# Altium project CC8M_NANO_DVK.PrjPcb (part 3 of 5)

## Sheet 12 - MIPI display and switch, MIPI camera.SchDoc: MIPI display and switch, MIPI camera
size A3; PageSetup: Record=PageOptions¦CenterHorizontal=True¦CenterVertical=True¦PrintScale=0.70¦XCorrection=1.00¦YCorrection=1.00¦PrintKind=0¦BorderSize=5000000¦LeftOffset=0¦BottomOffset=0¦Orientation=2¦PaperLength=4200¦PaperWidth=2970¦Scale=100¦PaperSource=7¦PrintQuality=600¦MediaType=1¦DitherType=10¦PaperKind=A4¦PrintScaleMode=1; Author: Juan Anzola; SheetNumber: 12; SheetTotal: 21
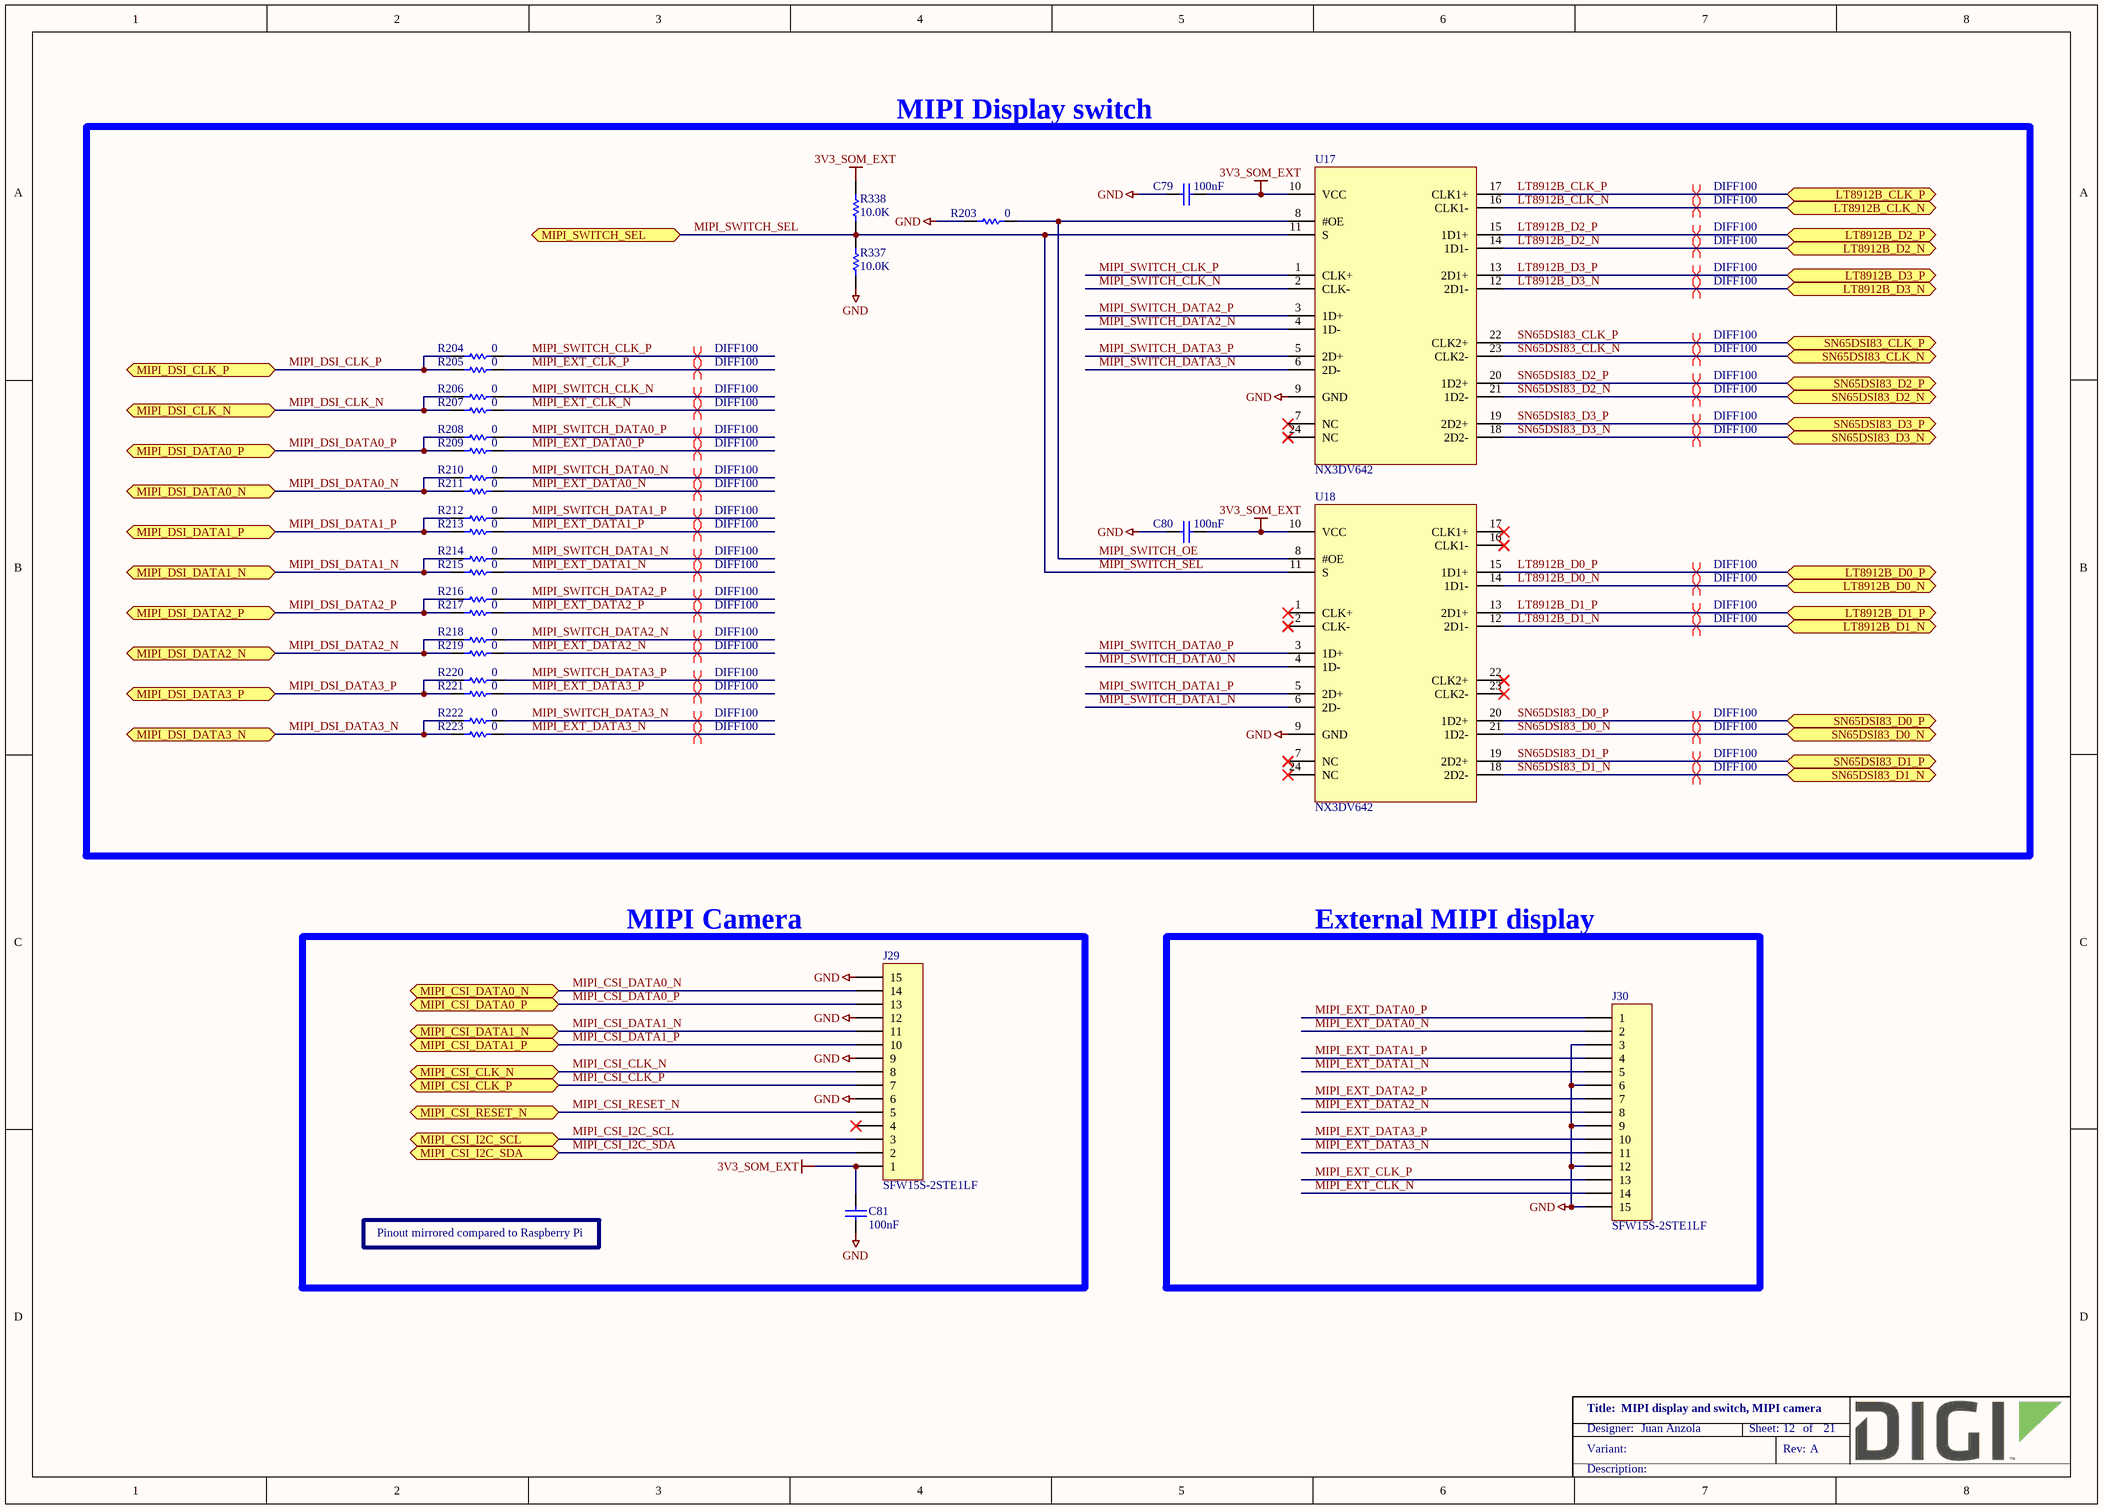
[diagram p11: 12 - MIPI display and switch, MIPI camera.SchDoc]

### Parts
C79  100nF  [CAPC1005X55N]
C80  100nF  [CAPC1005X55N]
C81  100nF  [CAPC1005X55N]
J29  SFW15S-2STE1LF  [FCI_SFW15S-2STE1LF]
J30  SFW15S-2STE1LF  [FCI_SFW15S-2STE1LF]
R203  0  [RESC1609X55N]
R204  0  [RESC1609X55N]
R205  0  [RESC1609X55N]
R206  0  [RESC1609X55N]
R207  0  [RESC1609X55N]
R208  0  [RESC1609X55N]
R209  0  [RESC1609X55N]
R210  0  [RESC1609X55N]
R211  0  [RESC1609X55N]
R212  0  [RESC1609X55N]
R213  0  [RESC1609X55N]
R214  0  [RESC1609X55N]
R215  0  [RESC1609X55N]
R216  0  [RESC1609X55N]
R217  0  [RESC1609X55N]
R218  0  [RESC1609X55N]
R219  0  [RESC1609X55N]
R220  0  [RESC1609X55N]
R221  0  [RESC1609X55N]
R222  0  [RESC1609X55N]
R223  0  [RESC1609X55N]
R337  10.0K  [RESC1005X40N]
R338  10.0K  [RESC1005X40N]
U17  NX3DV642  [QFN40P340X250X50-24N]
U18  NX3DV642  [QFN40P340X250X50-24N]

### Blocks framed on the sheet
MIPI Display switch: C79 C80 R203-R223 R337 R338 U17 U18
MIPI Camera: C81 J29
External MIPI display: J30

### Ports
LT8912B_CLK_N (bidir), LT8912B_CLK_P (bidir), LT8912B_D0_N (bidir), LT8912B_D0_P (bidir), LT8912B_D1_N (bidir), LT8912B_D1_P (bidir), LT8912B_D2_N (bidir), LT8912B_D2_P (bidir), LT8912B_D3_N (bidir), LT8912B_D3_P (bidir), MIPI_CSI_CLK_N (bidir), MIPI_CSI_CLK_P (bidir), MIPI_CSI_DATA0_N (bidir), MIPI_CSI_DATA0_P (bidir), MIPI_CSI_DATA1_N (bidir), MIPI_CSI_DATA1_P (bidir), MIPI_CSI_I2C_SCL (bidir), MIPI_CSI_I2C_SDA (bidir), MIPI_CSI_RESET_N (bidir), MIPI_DSI_CLK_N (bidir), MIPI_DSI_CLK_P (bidir), MIPI_DSI_DATA0_N (bidir), MIPI_DSI_DATA0_P (bidir), MIPI_DSI_DATA1_N (bidir), MIPI_DSI_DATA1_P (bidir), MIPI_DSI_DATA2_N (bidir), MIPI_DSI_DATA2_P (bidir), MIPI_DSI_DATA3_N (bidir), MIPI_DSI_DATA3_P (bidir), MIPI_SWITCH_SEL (bidir), SN65DSI83_CLK_N (bidir), SN65DSI83_CLK_P (bidir), SN65DSI83_D0_N (bidir), SN65DSI83_D0_P (bidir), SN65DSI83_D1_N (bidir), SN65DSI83_D1_P (bidir), SN65DSI83_D2_N (bidir), SN65DSI83_D2_P (bidir), SN65DSI83_D3_N (bidir), SN65DSI83_D3_P (bidir)

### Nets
3V3_SOM_EXT: C79.1 C80.1 C81.2 J29.1 R338.1 U17.10(VCC) U18.10(VCC)
GND: C79.2 C80.2 C81.1 J29.6 J29.9 J29.12 J29.15 J30.3 J30.6 J30.9 J30.12 J30.15 R203.1 R337.2 U17.9(GND) U18.9(GND)
LT8912B_CLK_N: U17.16(CLK1-) ; port LT8912B_CLK_N
LT8912B_CLK_P: U17.17(CLK1+) ; port LT8912B_CLK_P
LT8912B_D0_N: U18.14(1D1-) ; port LT8912B_D0_N
LT8912B_D0_P: U18.15(1D1+) ; port LT8912B_D0_P
LT8912B_D1_N: U18.12(2D1-) ; port LT8912B_D1_N
LT8912B_D1_P: U18.13(2D1+) ; port LT8912B_D1_P
LT8912B_D2_N: U17.14(1D1-) ; port LT8912B_D2_N
LT8912B_D2_P: U17.15(1D1+) ; port LT8912B_D2_P
LT8912B_D3_N: U17.12(2D1-) ; port LT8912B_D3_N
LT8912B_D3_P: U17.13(2D1+) ; port LT8912B_D3_P
MIPI_CSI_CLK_N: J29.8 ; port MIPI_CSI_CLK_N
MIPI_CSI_CLK_P: J29.7 ; port MIPI_CSI_CLK_P
MIPI_CSI_DATA0_N: J29.14 ; port MIPI_CSI_DATA0_N
MIPI_CSI_DATA0_P: J29.13 ; port MIPI_CSI_DATA0_P
MIPI_CSI_DATA1_N: J29.11 ; port MIPI_CSI_DATA1_N
MIPI_CSI_DATA1_P: J29.10 ; port MIPI_CSI_DATA1_P
MIPI_CSI_I2C_SCL: J29.3 ; port MIPI_CSI_I2C_SCL
MIPI_CSI_I2C_SDA: J29.2 ; port MIPI_CSI_I2C_SDA
MIPI_CSI_RESET_N: J29.5 ; port MIPI_CSI_RESET_N
MIPI_DSI_CLK_N: R206.1 R207.1 ; port MIPI_DSI_CLK_N
MIPI_DSI_CLK_P: R204.1 R205.1 ; port MIPI_DSI_CLK_P
MIPI_DSI_DATA0_N: R210.1 R211.1 ; port MIPI_DSI_DATA0_N
MIPI_DSI_DATA0_P: R208.1 R209.1 ; port MIPI_DSI_DATA0_P
MIPI_DSI_DATA1_N: R214.1 R215.1 ; port MIPI_DSI_DATA1_N
MIPI_DSI_DATA1_P: R212.1 R213.1 ; port MIPI_DSI_DATA1_P
MIPI_DSI_DATA2_N: R218.1 R219.1 ; port MIPI_DSI_DATA2_N
MIPI_DSI_DATA2_P: R216.1 R217.1 ; port MIPI_DSI_DATA2_P
MIPI_DSI_DATA3_N: R222.1 R223.1 ; port MIPI_DSI_DATA3_N
MIPI_DSI_DATA3_P: R220.1 R221.1 ; port MIPI_DSI_DATA3_P
MIPI_EXT_CLK_N: J30.14 R207.2
MIPI_EXT_CLK_P: J30.13 R205.2
MIPI_EXT_DATA0_N: J30.2 R211.2
MIPI_EXT_DATA0_P: J30.1 R209.2
MIPI_EXT_DATA1_N: J30.5 R215.2
MIPI_EXT_DATA1_P: J30.4 R213.2
MIPI_EXT_DATA2_N: J30.8 R219.2
MIPI_EXT_DATA2_P: J30.7 R217.2
MIPI_EXT_DATA3_N: J30.11 R223.2
MIPI_EXT_DATA3_P: J30.10 R221.2
MIPI_SWITCH_CLK_N: R206.2 U17.2(CLK-)
MIPI_SWITCH_CLK_P: R204.2 U17.1(CLK+)
MIPI_SWITCH_DATA0_N: R210.2 U18.4(1D-)
MIPI_SWITCH_DATA0_P: R208.2 U18.3(1D+)
MIPI_SWITCH_DATA1_N: R214.2 U18.6(2D-)
MIPI_SWITCH_DATA1_P: R212.2 U18.5(2D+)
MIPI_SWITCH_DATA2_N: R218.2 U17.4(1D-)
MIPI_SWITCH_DATA2_P: R216.2 U17.3(1D+)
MIPI_SWITCH_DATA3_N: R222.2 U17.6(2D-)
MIPI_SWITCH_DATA3_P: R220.2 U17.5(2D+)
MIPI_SWITCH_OE: R203.2 U17.8(#OE) U18.8(#OE)
MIPI_SWITCH_SEL: R337.1 R338.2 U17.11(S) U18.11(S) ; port MIPI_SWITCH_SEL
SN65DSI83_CLK_N: U17.23(CLK2-) ; port SN65DSI83_CLK_N
SN65DSI83_CLK_P: U17.22(CLK2+) ; port SN65DSI83_CLK_P
SN65DSI83_D0_N: U18.21(1D2-) ; port SN65DSI83_D0_N
SN65DSI83_D0_P: U18.20(1D2+) ; port SN65DSI83_D0_P
SN65DSI83_D1_N: U18.18(2D2-) ; port SN65DSI83_D1_N
SN65DSI83_D1_P: U18.19(2D2+) ; port SN65DSI83_D1_P
SN65DSI83_D2_N: U17.21(1D2-) ; port SN65DSI83_D2_N
SN65DSI83_D2_P: U17.20(1D2+) ; port SN65DSI83_D2_P
SN65DSI83_D3_N: U17.18(2D2-) ; port SN65DSI83_D3_N
SN65DSI83_D3_P: U17.19(2D2+) ; port SN65DSI83_D3_P

Not connected (* = marked no-connect by the designer): J29 4*; U17 7(NC)* 24(NC)*; U18 1(CLK+)* 2(CLK-)* 7(NC)* 16(CLK1-)* 17(CLK1+)* 22(CLK2+)* 23(CLK2-)* 24(NC)*

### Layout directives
differential pair; net class DIFF100: LT8912B_CLK_N, LT8912B_CLK_P, LT8912B_D0_N, LT8912B_D0_P, LT8912B_D1_N, LT8912B_D1_P, LT8912B_D2_N, LT8912B_D2_P, LT8912B_D3_N, LT8912B_D3_P, MIPI_EXT_CLK_N, MIPI_EXT_CLK_P, MIPI_EXT_DATA0_N, MIPI_EXT_DATA0_P, MIPI_EXT_DATA1_N, MIPI_EXT_DATA1_P, MIPI_EXT_DATA2_N, MIPI_EXT_DATA2_P, MIPI_EXT_DATA3_N, MIPI_EXT_DATA3_P, MIPI_SWITCH_CLK_N, MIPI_SWITCH_CLK_P, MIPI_SWITCH_DATA0_N, MIPI_SWITCH_DATA0_P, MIPI_SWITCH_DATA1_N, MIPI_SWITCH_DATA1_P, MIPI_SWITCH_DATA2_N, MIPI_SWITCH_DATA2_P, MIPI_SWITCH_DATA3_N, MIPI_SWITCH_DATA3_P, SN65DSI83_CLK_N, SN65DSI83_CLK_P, SN65DSI83_D0_N, SN65DSI83_D0_P, SN65DSI83_D1_N, SN65DSI83_D1_P, SN65DSI83_D2_N, SN65DSI83_D2_P, SN65DSI83_D3_N, SN65DSI83_D3_P

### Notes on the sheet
- Pinout mirrored compared to Raspberry Pi

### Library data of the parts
C79-C81 = 1000006: CAP 100nF 16V 10% X7R 0402; Part_Type: Capacitor; Manufacturer: Murata; Manufacturer_Part_Number: GRM155R71C104KA88D; Digi_PN: 14050552; Component_Life_Cycle_State: CAD Reviewed; Area: 0,95; Project: KITT; Tolerance: 10
J29 J30 = 1001866: CONN FFC FPC VERT 15POS 1MM SMD; Part_Type: Connector; Manufacturer: FCI; Digi_PN: 18000730; Component_Life_Cycle_State: Reviewed; Area: 128,76; Project: CCiMX6 SBC MFG TEST BOARD
R203-R223 = 1000208: RES 0.0 OHM 1/10W 0603; Part_Type: Resistor; Manufacturer: Panasonic - ECG; Manufacturer_Part_Number: ERJ-3GEY0R00V; Note: 13051103 = Digi No. for GE WDNU; Digi_PN: 13050568; Component_Life_Cycle_State: Reviewed; Area: 2,5; Voltage: 75V
R337 R338 = 1000537: RES 10.0K OHM 1/10W 1% 0402 SMD; Part_Type: Resistor; Manufacturer: Panasonic - ECG; Manufacturer_Part_Number: ERJ-2RKF1002X; Digi_PN: 13051084; Component_Life_Cycle_State: CAD Reviewed; Area: 0,95; Power_WV_SRF: 100
U17 U18 = 1002697: IC SWITCH TPDT DIFF XQFN24; Manufacturer: NXP Semiconductors; Digi_PN: 16000171; Component_Life_Cycle_State: Reviewed; Area: 17,35

## Sheet 13 - MIPI to HDMI bridge.SchDoc: MIPI to HDMI bridge
size A3; PageSetup: Record=PageOptions¦CenterHorizontal=True¦CenterVertical=True¦PrintScale=0.70¦XCorrection=1.00¦YCorrection=1.00¦PrintKind=0¦BorderSize=5000000¦LeftOffset=0¦BottomOffset=0¦Orientation=2¦PaperLength=4200¦PaperWidth=2970¦Scale=100¦PaperSource=7¦PrintQuality=600¦MediaType=1¦DitherType=10¦PaperKind=A4¦PrintScaleMode=1; Author: Juan Anzola; SheetNumber: 13; SheetTotal: 21
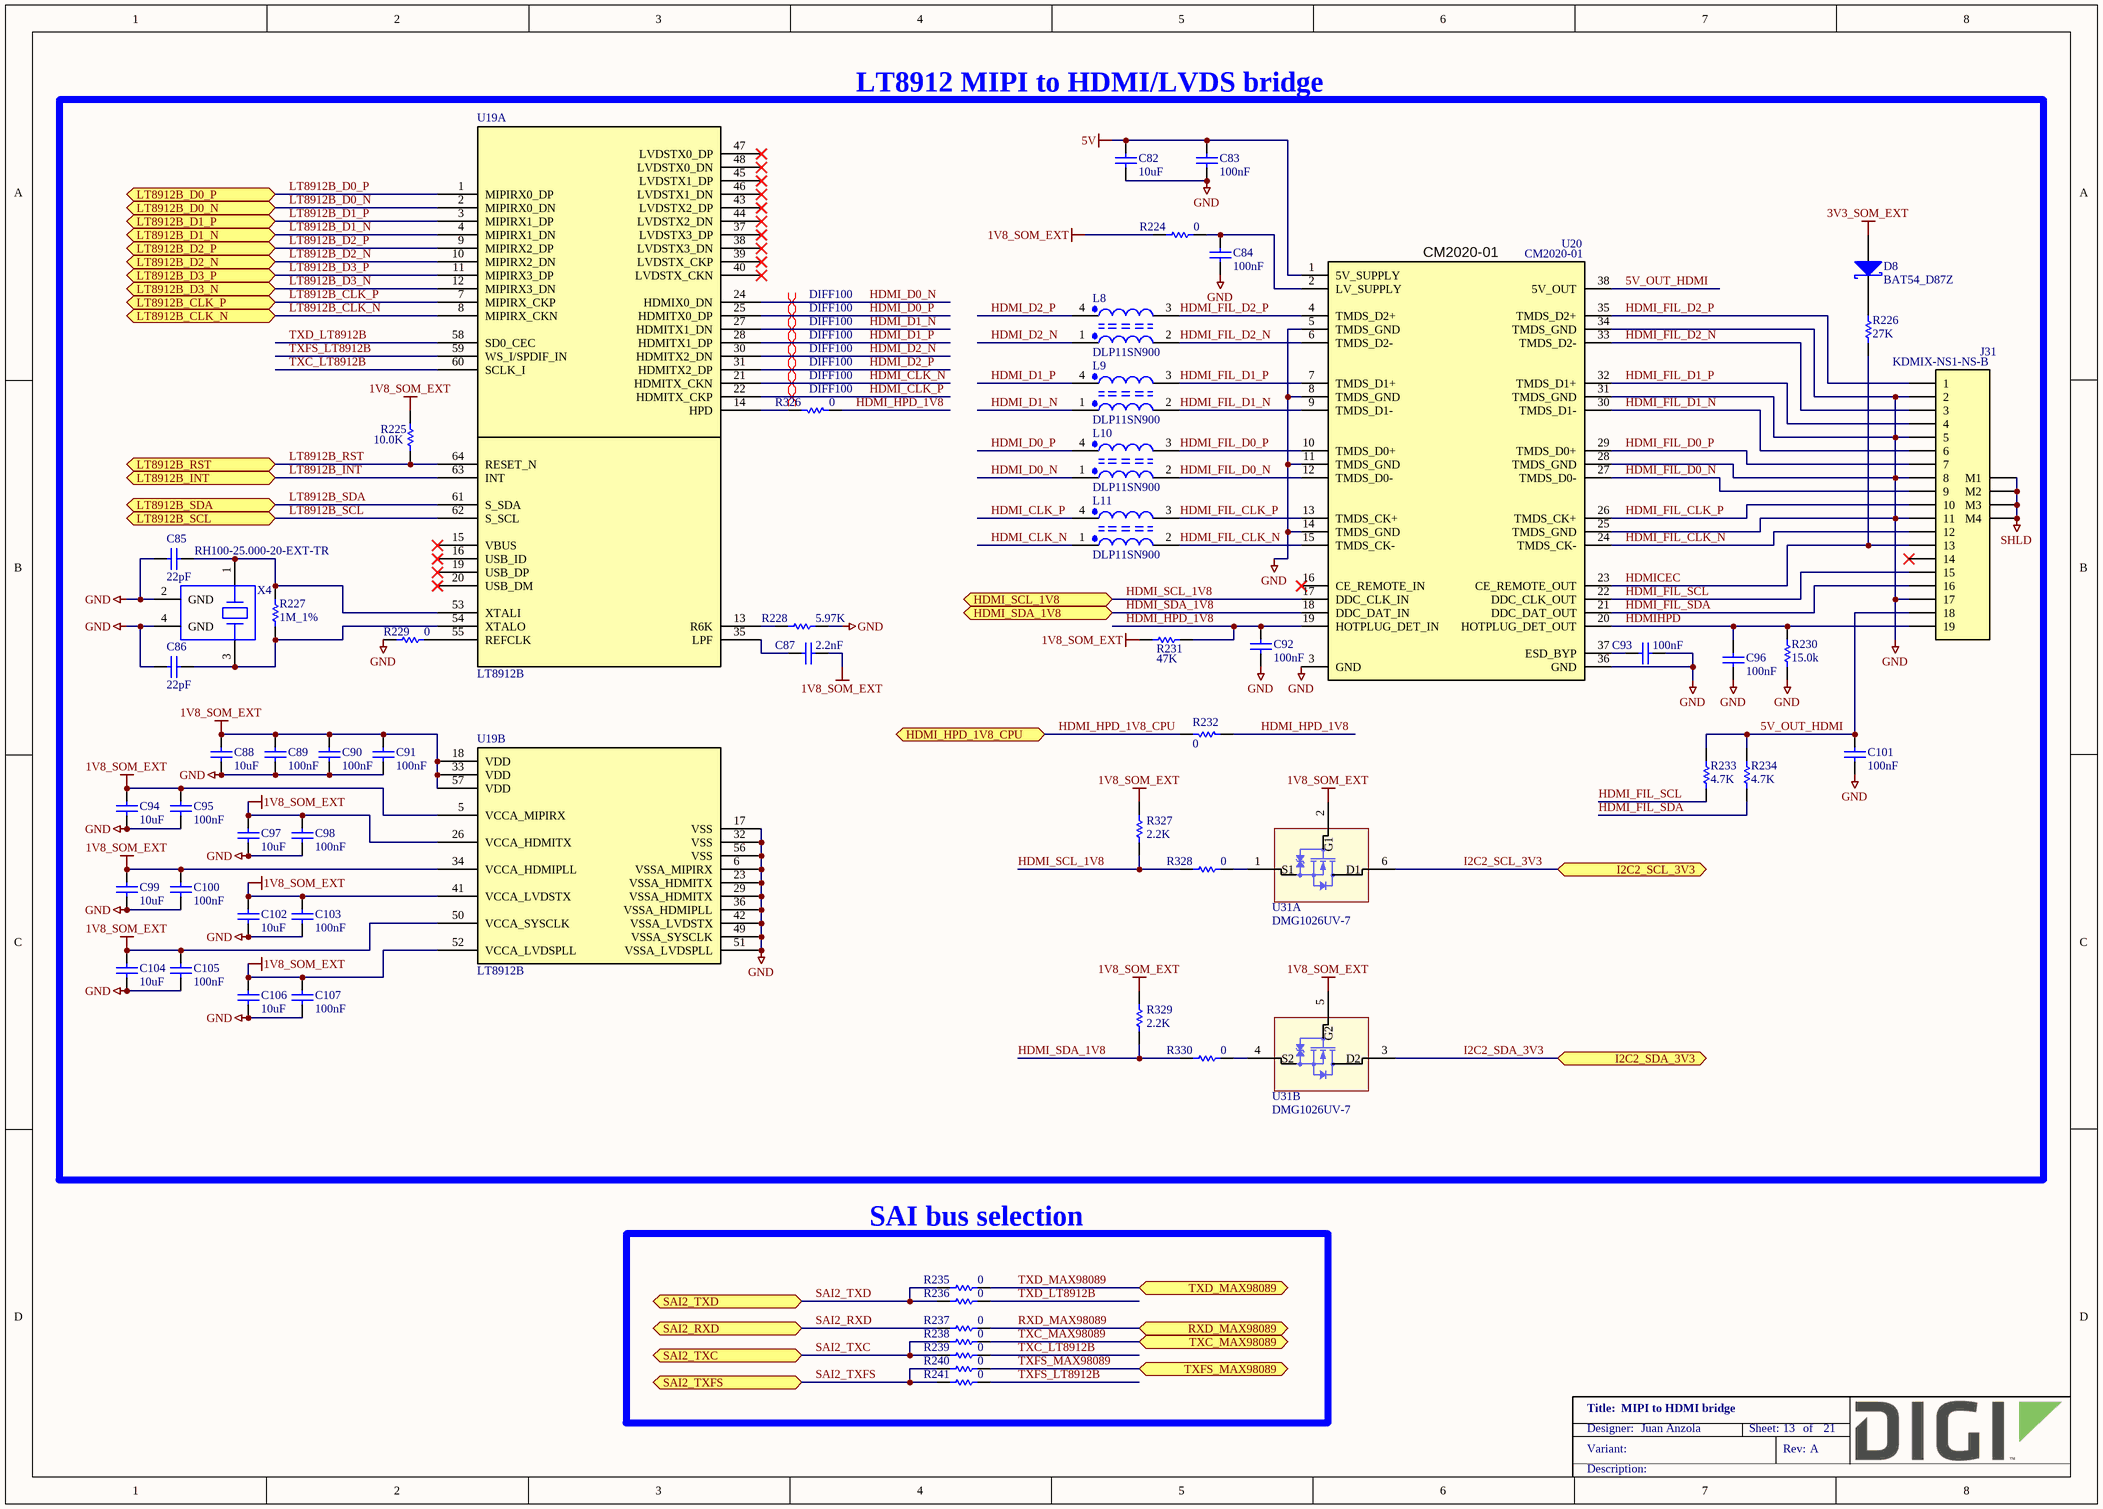
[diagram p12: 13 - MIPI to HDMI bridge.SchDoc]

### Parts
C82  10uF  [CAPC1005X55N]
C83  100nF  [CAPC1005X55N]
C84  100nF  [CAPC1005X55N]
C85  22pF  [CAPC1005X55N]
C86  22pF  [CAPC1005X55N]
C87  2.2nF  [CAPC1608X90N]
C88  10uF  [CAPC1005X55N]
C89  100nF  [CAPC1005X55N]
C90  100nF  [CAPC1005X55N]
C91  100nF  [CAPC1005X55N]
C92  100nF  [CAPC1005X55N]
C93  100nF  [CAPC1005X55N]
C94  10uF  [CAPC1005X55N]
C95  100nF  [CAPC1005X55N]
C96  100nF  [CAPC1005X55N]
C97  10uF  [CAPC1005X55N]
C98  100nF  [CAPC1005X55N]
C99  10uF  [CAPC1005X55N]
C100  100nF  [CAPC1005X55N]
C101  100nF  [CAPC1005X55N]
C102  10uF  [CAPC1005X55N]
C103  100nF  [CAPC1005X55N]
C104  10uF  [CAPC1005X55N]
C105  100nF  [CAPC1005X55N]
C106  10uF  [CAPC1005X55N]
C107  100nF  [CAPC1005X55N]
D8  BAT54_D87Z  [SOT95P240X110_AXK-3N]
J31  KDMIX-NS1-NS-B  [KYCON_KDMIX]
L8  DLP11SN900  [FIL_DLP11S]
L9  DLP11SN900  [FIL_DLP11S]
L10  DLP11SN900  [FIL_DLP11S]
L11  DLP11SN900  [FIL_DLP11S]
R224  0  [RESC1005X40N]
R225  10.0K  [RESC1005X40N]
R226  27K  [RESC1005X40N]
R227  1M_1%  [RESC1005X40N]
R228  5.97K  [RESC1005X40N]
R229  0  [RESC1005X40N]
R230  15.0k  [RESC1005X40N]
R231  47K  [RESC1005X40N]
R232  0  [RESC1005X40N]
R233  4.7K  [RESC1005X40N]
R234  4.7K  [RESC1005X40N]
R235  0  [RESC1609X55N]
R236  0  [RESC1609X55N]
R237  0  [RESC1609X55N]
R238  0  [RESC1609X55N]
R239  0  [RESC1609X55N]
R240  0  [RESC1609X55N]
R241  0  [RESC1609X55N]
R326  0  [RESC1005X40N]
R327  2.2K  [RESC1005X40N]
R328  0  [RESC1005X40N]
R329  2.2K  [RESC1005X40N]
R330  0  [RESC1005X40N]
U19  LT8912B  [QFN40P750X750X80-64N]  (parts A,B of 2)
U20  CM2020-01  [SOP50P640X120-38N]
U31  DMG1026UV-7  [SOTFL50P160X60-6N]  (parts A,B of 2)
X4  RH100-25.000-20-EXT-TR  [OSC210P320X250X90-4N]

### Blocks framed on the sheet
LT8912 MIPI to HDMI/LVDS bridge: C82-C107 D8 J31 L8-L11 R224-R234 R326-R330 U19 U20 U31 X4
SAI bus selection: R235-R241

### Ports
HDMI_HPD_1V8_CPU (bidir), HDMI_SCL_1V8 (bidir), HDMI_SDA_1V8 (bidir), I2C2_SCL_3V3 (bidir), I2C2_SDA_3V3 (bidir), LT8912B_CLK_N (bidir), LT8912B_CLK_P (bidir), LT8912B_D0_N (bidir), LT8912B_D0_P (bidir), LT8912B_D1_N (bidir), LT8912B_D1_P (bidir), LT8912B_D2_N (bidir), LT8912B_D2_P (bidir), LT8912B_D3_N (bidir), LT8912B_D3_P (bidir), LT8912B_INT (bidir), LT8912B_RST (bidir), LT8912B_SCL (bidir), LT8912B_SDA (bidir), RXD_MAX98089 (bidir), SAI2_RXD (bidir), SAI2_TXC (bidir), SAI2_TXD (bidir), SAI2_TXFS (bidir), TXC_MAX98089 (bidir), TXD_MAX98089 (bidir), TXFS_MAX98089 (bidir)

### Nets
1V8_SOM_EXT: C87.2 C88.2 C89.2 C90.2 C91.2 C94.2 C95.2 C97.2 C98.2 C99.2 C100.2 C102.2 C103.2 C104.2 C105.2 C106.2 C107.2 R224.2 R225.1 R231.1 R327.2 R329.2 U19.5(VCCA_MIPIRX) U19.18(VDD) U19.26(VCCA_HDMITX) U19.33(VDD) U19.34(VCCA_HDMIPLL) U19.41(VCCA_LVDSTX) U19.50(VCCA_SYSCLK) U19.52(VCCA_LVDSPLL) U19.57(VDD) U31.2(G1) U31.5(G2)
3V3_SOM_EXT: D8.A
5V: C82.2 C83.2 U20.1(5V_SUPPLY)
GND: C82.1 C83.1 C84.1 C85.1 C86.1 C88.1 C89.1 C90.1 C91.1 C92.1 C93.1 C94.1 C95.1 C96.1 C97.1 C98.1 C99.1 C100.1 C101.1 C102.1 C103.1 C104.1 C105.1 C106.1 C107.1 J31.2 J31.5 J31.8 J31.11 J31.17 R228.2 R229.1 R230.1 U19.6(VSSA_MIPIRX) U19.17(VSS) U19.23(VSSA_HDMITX) U19.29(VSSA_HDMITX) U19.32(VSS) U19.36(VSSA_HDMIPLL) U19.42(VSSA_LVDSTX) U19.49(VSSA_SYSCLK) U19.51(VSSA_LVDSPLL) U19.56(VSS) U20.3(GND) U20.5(TMDS_GND) U20.8(TMDS_GND) U20.11(TMDS_GND) U20.14(TMDS_GND) U20.25(TMDS_GND) U20.28(TMDS_GND) U20.31(TMDS_GND) U20.34(TMDS_GND) U20.36(GND) X4.2(GND) X4.4(GND)
SHLD: J31.M1 J31.M2 J31.M3 J31.M4
5V_OUT_HDMI: C101.2 J31.18 R233.1 R234.1 U20.38(5V_OUT)
HDMI_CLK_N: L11.1 U19.21(HDMITX_CKN)
HDMI_CLK_P: L11.4 U19.22(HDMITX_CKP)
HDMI_D0_N: L10.1 U19.24(HDMIX0_DN)
HDMI_D0_P: L10.4 U19.25(HDMITX0_DP)
HDMI_D1_N: L9.1 U19.27(HDMITX1_DN)
HDMI_D1_P: L9.4 U19.28(HDMITX1_DP)
HDMI_D2_N: L8.1 U19.30(HDMITX2_DN)
HDMI_D2_P: L8.4 U19.31(HDMITX2_DP)
HDMI_FIL_CLK_N: J31.12 L11.2 U20.15(TMDS_CK-) U20.24(TMDS_CK-)
HDMI_FIL_CLK_P: J31.10 L11.3 U20.13(TMDS_CK+) U20.26(TMDS_CK+)
HDMI_FIL_D0_N: J31.9 L10.2 U20.12(TMDS_D0-) U20.27(TMDS_D0-)
HDMI_FIL_D0_P: J31.7 L10.3 U20.10(TMDS_D0+) U20.29(TMDS_D0+)
HDMI_FIL_D1_N: J31.6 L9.2 U20.9(TMDS_D1-) U20.30(TMDS_D1-)
HDMI_FIL_D1_P: J31.4 L9.3 U20.7(TMDS_D1+) U20.32(TMDS_D1+)
HDMI_FIL_D2_N: J31.3 L8.2 U20.6(TMDS_D2-) U20.33(TMDS_D2-)
HDMI_FIL_D2_P: J31.1 L8.3 U20.4(TMDS_D2+) U20.35(TMDS_D2+)
HDMI_FIL_SCL: J31.15 R233.2 U20.22(DDC_CLK_OUT)
HDMI_FIL_SDA: J31.16 R234.2 U20.21(DDC_DAT_OUT)
HDMI_HPD_1V8: C92.2 R231.2 R232.1 R326.1 U20.19(HOTPLUG_DET_IN)
HDMI_HPD_1V8_CPU: R232.2 ; port HDMI_HPD_1V8_CPU
HDMI_SCL_1V8: R327.1 R328.1 U20.17(DDC_CLK_IN) ; port HDMI_SCL_1V8
HDMI_SDA_1V8: R329.1 R330.1 U20.18(DDC_DAT_IN) ; port HDMI_SDA_1V8
HDMICEC: J31.13 R226.2 U20.23(CE_REMOTE_OUT)
HDMIHPD: C96.2 J31.19 R230.2 U20.20(HOTPLUG_DET_OUT)
I2C2_SCL_3V3: U31.6(D1) ; port I2C2_SCL_3V3
I2C2_SDA_3V3: U31.3(D2) ; port I2C2_SDA_3V3
LT8912B_CLK_N: U19.8(MIPIRX_CKN) ; port LT8912B_CLK_N
LT8912B_CLK_P: U19.7(MIPIRX_CKP) ; port LT8912B_CLK_P
LT8912B_D0_N: U19.2(MIPIRX0_DN) ; port LT8912B_D0_N
LT8912B_D0_P: U19.1(MIPIRX0_DP) ; port LT8912B_D0_P
LT8912B_D1_N: U19.4(MIPIRX1_DN) ; port LT8912B_D1_N
LT8912B_D1_P: U19.3(MIPIRX1_DP) ; port LT8912B_D1_P
LT8912B_D2_N: U19.10(MIPIRX2_DN) ; port LT8912B_D2_N
LT8912B_D2_P: U19.9(MIPIRX2_DP) ; port LT8912B_D2_P
LT8912B_D3_N: U19.12(MIPIRX3_DN) ; port LT8912B_D3_N
LT8912B_D3_P: U19.11(MIPIRX3_DP) ; port LT8912B_D3_P
LT8912B_INT: U19.63(INT) ; port LT8912B_INT
LT8912B_RST: R225.2 U19.64(RESET_N) ; port LT8912B_RST
LT8912B_SCL: U19.62(S_SCL) ; port LT8912B_SCL
LT8912B_SDA: U19.61(S_SDA) ; port LT8912B_SDA
RXD_MAX98089: R237.2 ; port RXD_MAX98089
SAI2_RXD: R237.1 ; port SAI2_RXD
SAI2_TXC: R238.1 R239.1 ; port SAI2_TXC
SAI2_TXD: R235.1 R236.1 ; port SAI2_TXD
SAI2_TXFS: R240.1 R241.1 ; port SAI2_TXFS
TXC_LT8912B: R239.2 U19.60(SCLK_I)
TXC_MAX98089: R238.2 ; port TXC_MAX98089
TXD_LT8912B: R236.2 U19.58(SD0_CEC)
TXD_MAX98089: R235.2 ; port TXD_MAX98089
TXFS_LT8912B: R241.2 U19.59(WS_I/SPDIF_IN)
TXFS_MAX98089: R240.2 ; port TXFS_MAX98089
NetC84_2: C84.2 R224.1 U20.2(LV_SUPPLY)
NetC85_2: C85.2 R227.2 U19.53(XTALI) X4.1
NetC86_2: C86.2 R227.1 U19.54(XTALO) X4.3
NetC87_1: C87.1 U19.35(LPF)
NetC93_2: C93.2 U20.37(ESD_BYP)
NetD8_K: D8.K R226.1
NetR228_1: R228.1 U19.13(R6K)
NetR229_2: R229.2 U19.55(REFCLK)
NetR326_2: R326.2 U19.14(HPD)
NetR328_2: R328.2 U31.1(S1)
NetR330_2: R330.2 U31.4(S2)

Not connected (* = marked no-connect by the designer): J31 14*; U19 15(VBUS)* 16(USB_ID)* 19(USB_DP)* 20(USB_DM)* 37(LVDSTX3_DP)* 38(LVDSTX3_DN)* 39(LVDSTX_CKP)* 40(LVDSTX_CKN)* 43(LVDSTX2_DP)* 44(LVDSTX2_DN)* 45(LVDSTX1_DP)* 46(LVDSTX1_DN)* 47(LVDSTX0_DP)* 48(LVDSTX0_DN)*; U20 16(CE_REMOTE_IN)*

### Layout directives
differential pair; net class DIFF100: HDMI_CLK_N, HDMI_CLK_P, HDMI_D0_N, HDMI_D0_P, HDMI_D1_N, HDMI_D1_P, HDMI_D2_N, HDMI_D2_P

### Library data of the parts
C82 C88 C94 C97 C99 C102 C104 C106 = 1001168: CAP CER 10UF 10V 20% X5R 0402; Part_Type: Capacitor; Manufacturer: Samsung; Manufacturer_Part_Number: CL05A106MP5NUNC; Digi_PN: 14050689; Component_Life_Cycle_State: Reviewed; Area: 0.95; Project: CCWMX6_SBC board
C83 C84 C89-C93 C95 C96 C98 C100 C101 C103 C105 C107 = 1000006: CAP 100nF 16V 10% X7R 0402; Part_Type: Capacitor; Manufacturer: Murata; Manufacturer_Part_Number: GRM155R71C104KA88D; Component_Life_Cycle_State: CAD Reviewed; Area: 0.95; Project: KITT; Tolerance: 10; Digi_PN: 14050552
C85 C86 = 1001166: CAP CER 22PF 50V 5% NP0 0402; Part_Type: Capacitor; Manufacturer: Murata; Manufacturer_Part_Number: GRM1555C1H220JA01D; Note: 14050749 = Digi No. for GE WDNU; Digi_PN: 14050367; Component_Life_Cycle_State: Reviewed; Area: 0,95; Project: CCWMX6_SBC board; Temp_Coef: C0G, NP0
C87 = 1002727: CAP CER 2200PF 50V X7R 5% 0603; Part_Type: Capacitor; Manufacturer: Kemet; Manufacturer_Part_Number: C0603C222J5RACTU; Digi_PN: 14050443; Component_Life_Cycle_State: Pending; Area: 2,27
D8 = 1001169: DIODE SCHOTTKY 30V 0.2A SOT23-3; Part_Type: IC; Manufacturer: Fairchild Semiconductor; Digi_PN: 17050507; Component_Life_Cycle_State: Reviewed; Area: 8; Project: CCWMX6_SBC board
J31 = 1001123: HDMI RECEPTACLE, SMT; Part_Type: Connector; Manufacturer: KYCON; Digi_PN: 18000451; Component_Life_Cycle_State: Reviewed; Area: 174; Project: CCWMX6_SBC board
L8-L11 = 1001014: CHOKE COIL COMMON MODE 150MA SMD; Part_Type: Inductor; Manufacturer: Murata; Manufacturer_Part_Number: DLP11SN900HL2L; Component_Life_Cycle_State: Reviewed; Area: 3.94; Project: ResMed RF Test Interface Board; Digi_PN: 21000531
R224 R229 R232 R326 = 1000076: RES 0.0 OHM 1/10W 0402 SMD; Part_Type: Resistor; Manufacturer: Panasonic - ECG; Manufacturer_Part_Number: ERJ-2GE0R00X; Digi_PN: 13050387; Component_Life_Cycle_State: Proven; Area: 0,95; Project: Adjustable Foundation; Power_WV_SRF: 10
R225 = 1000537: RES 10.0K OHM 1/10W 1% 0402 SMD; Part_Type: Resistor; Manufacturer: Panasonic - ECG; Manufacturer_Part_Number: ERJ-2RKF1002X; Component_Life_Cycle_State: CAD Reviewed; Area: 0.95; Project: KITT; Power_WV_SRF: 100; Digi_PN: 13051084
R226 = 1001153: RES 27.0K OHM 1/16W 1% 0402 SMD; Part_Type: Resistor; Manufacturer: Yageo; Manufacturer_Part_Number: RC0402FR-0727KL; Digi_PN: 13050609; Component_Life_Cycle_State: Reviewed; Area: 0.95; Project: CCWMX6_SBC board
R227 = 1000971: RES 1.00M OHM 1/16W 1% 0402 SMD; Part_Type: Resistor; Manufacturer: Yageo; Manufacturer_Part_Number: RC0402FR-071ML; Note: 13051098 = Digi No. for GE WDNU; Digi_PN: 13050561; Component_Life_Cycle_State: Reviewed; Area: 0,95; Power_WV_SRF: 63; Tolerance: 1
R228 = 1002748: RES 5.97K OHM 0.1% 1/10W 0402; Part_Type: Resistor; Manufacturer: Vishay Dale; Manufacturer_Part_Number: TNPW04025K97BEED; Digi_PN: 13000099; Component_Life_Cycle_State: Created; Area: 0,95
R230 = 1000174: RES 15.0K OHM 1/10W 1% 0402 SMD; Part_Type: Resistor; Manufacturer: Panasonic - ECG; Manufacturer_Part_Number: ERJ-2RKF1502X; Component_Life_Cycle_State: CAD Reviewed; Area: 0.95; Project: KITT; Power_WV_SRF: 10; Digi_PN: 13050446
R231 = 1001155: RES 47.0K OHM 1/16W 1% 0402 SMD; Part_Type: Resistor; Manufacturer: Vishay Dale; Manufacturer_Part_Number: CRCW040247K0FKED; Digi_PN: 13050646; Component_Life_Cycle_State: Reviewed; Area: 0.95; Project: CCWMX6_SBC board
R233 R234 = 1000038: RES 4.7K OHM 1/10W 5% 0402 SMD; Part_Type: Resistor; Manufacturer: Panasonic - ECG; Manufacturer_Part_Number: ERJ-2GEJ472X; Component_Life_Cycle_State: Proven; Area: 0.95; Project: Adjustable Foundation; Power_WV_SRF: 100; Tolerance: 5; Digi_PN: 13050549
R235-R241 = 1000208: as R203-R223 on sheet 12 - MIPI display and switch, MIPI camera
R327 R329 = 1001156: RES 2.20K OHM 1/16W 1% 0402 SMD; Part_Type: Resistor; Manufacturer: Yageo; Manufacturer_Part_Number: RC0402FR-072K2L; Digi_PN: 13050699; Component_Life_Cycle_State: Reviewed; Area: 0.95; Project: CCWMX6_SBC board; Note: 13051099 = Digi No. for GE WDNU
R328 R330 = 1000076: RES 0.0 OHM 1/10W 0402 SMD; Part_Type: Resistor; Manufacturer: Panasonic - ECG; Manufacturer_Part_Number: ERJ-2GE0R00X; Component_Life_Cycle_State: Proven; Area: 0.95; Project: Adjustable Foundation; Power_WV_SRF: 10; Digi_PN: 13050387
U19 = 1002722: MIPI DSI BRIDGE TO LVDS/HDMI SINGLE CHANNEL; Part_Type: IC; Manufacturer: Lontium Semiconductor; Digi_PN: 16000199; Component_Life_Cycle_State: Pending; Area: 76,04
U20 = 1001125: IC HDMI XMITTER PORT P/I 38TSSOP; Manufacturer: On Semiconductor; Digi_PN: 16051861; Component_Life_Cycle_State: Reviewed; Area: 43; Project: CCWMX6_SBC board
U31 = 1001009: MOSFET DL N-CH 60V 410MA SOT-563; Part_Type: Transistor; Manufacturer: Diodes, Inc.; Digi_PN: 17050796; Component_Life_Cycle_State: Reviewed; Area: 2,89; Project: ConnectCore i.MX6 module
X4 = 1001497: SMCRY,25MHZ 50PPM 20PF RH100 EXT; Part_Type: Crystals-Oscillators; Manufacturer: Raltron; Digi_PN: 20000285; Component_Life_Cycle_State: Reviewed; Area: 3,2; Project: CCWMX6_SBC board

## Sheet 14 - MIPI to LVDS bridge.SchDoc: MIPI to LVDS bridge
size A3; PageSetup: Record=PageOptions¦CenterHorizontal=True¦CenterVertical=True¦PrintScale=0.70¦XCorrection=1.00¦YCorrection=1.00¦PrintKind=0¦BorderSize=5000000¦LeftOffset=0¦BottomOffset=0¦Orientation=2¦PaperLength=4200¦PaperWidth=2970¦Scale=100¦PaperSource=7¦PrintQuality=600¦MediaType=1¦DitherType=10¦PaperKind=A4¦PrintScaleMode=1; Author: Juan Anzola; SheetNumber: 14; SheetTotal: 21
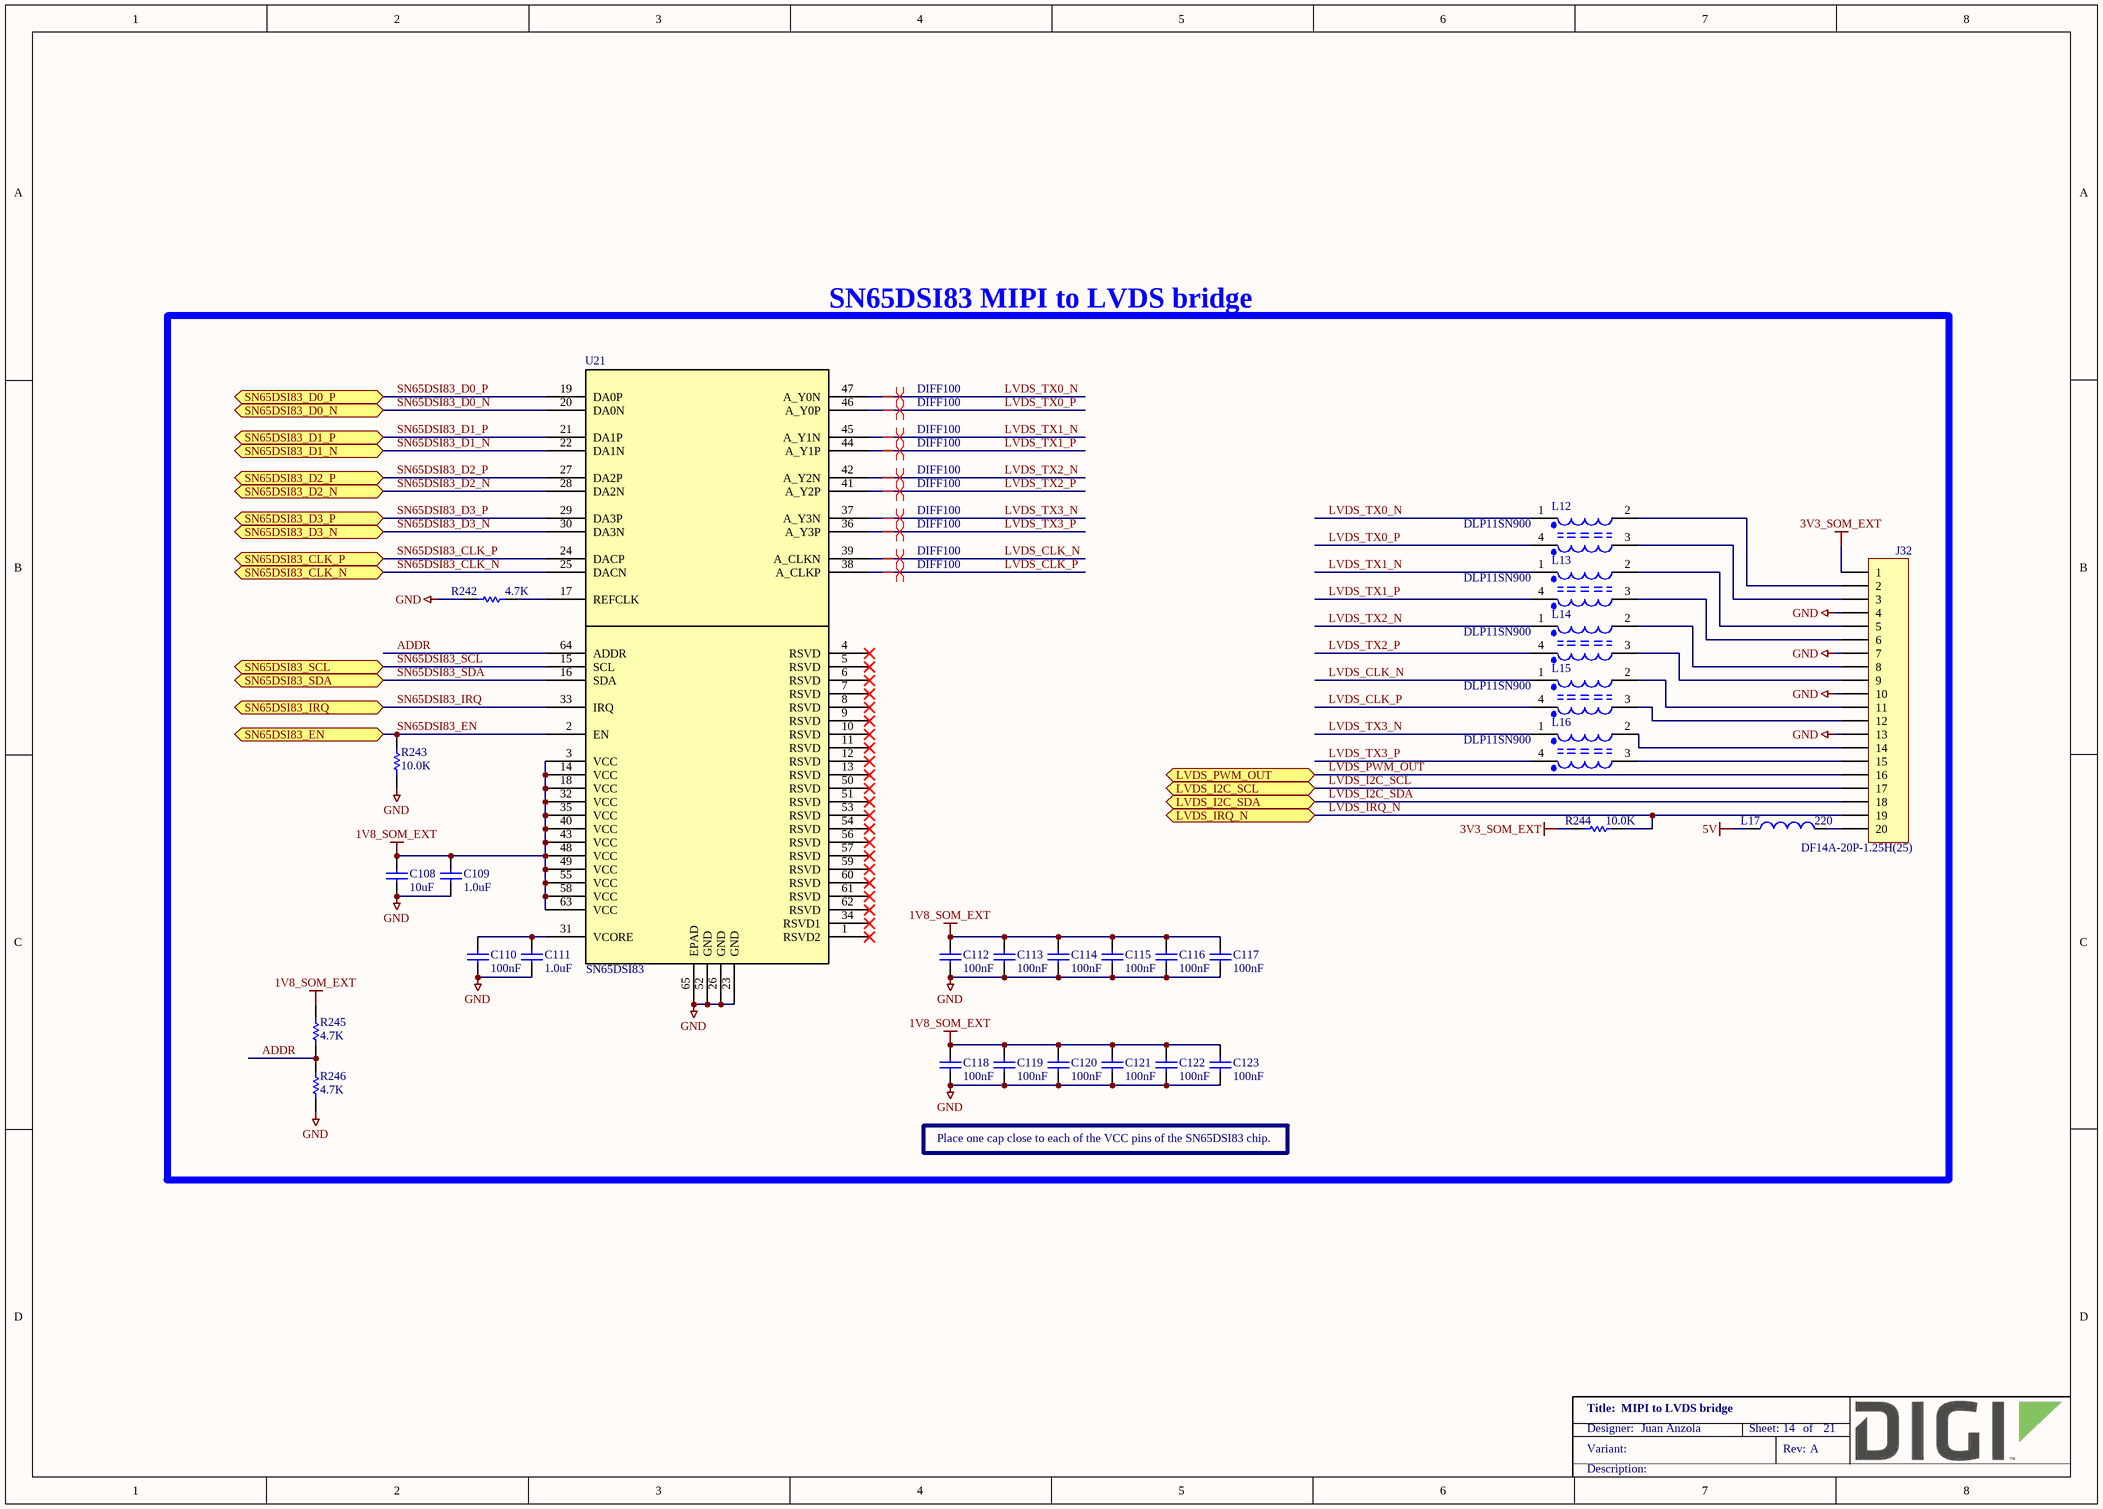
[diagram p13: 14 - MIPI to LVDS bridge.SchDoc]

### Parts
C108  10uF  [CAPC1005X55N]
C109  1.0uF  [CAPC1005X55N]
C110  100nF  [CAPC1005X55N]
C111  1.0uF  [CAPC1005X55N]
C112  100nF  [CAPC1005X55N]
C113  100nF  [CAPC1005X55N]
C114  100nF  [CAPC1005X55N]
C115  100nF  [CAPC1005X55N]
C116  100nF  [CAPC1005X55N]
C117  100nF  [CAPC1005X55N]
C118  100nF  [CAPC1005X55N]
C119  100nF  [CAPC1005X55N]
C120  100nF  [CAPC1005X55N]
C121  100nF  [CAPC1005X55N]
C122  100nF  [CAPC1005X55N]
C123  100nF  [CAPC1005X55N]
J32  DF14A-20P-1.25H(25)  [HIROSE_DF14A-20P-1.25H]
L12  DLP11SN900  [FIL_DLP11S]
L13  DLP11SN900  [FIL_DLP11S]
L14  DLP11SN900  [FIL_DLP11S]
L15  DLP11SN900  [FIL_DLP11S]
L16  DLP11SN900  [FIL_DLP11S]
L17  220  [INDC2013X110N]
R242  4.7K  [RESC1005X40N]
R243  10.0K  [RESC1005X40N]
R244  10.0K  [RESC1005X40N]
R245  4.7K  [RESC1005X40N]
R246  4.7K  [RESC1005X40N]
U21  SN65DSI83  [QFP50P1200X1200X120-65L30T320N]

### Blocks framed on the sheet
SN65DSI83 MIPI to LVDS bridge: C108-C123 J32 L12-L17 R242-R246 U21

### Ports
LVDS_I2C_SCL (bidir), LVDS_I2C_SDA (bidir), LVDS_IRQ_N (bidir), LVDS_PWM_OUT (bidir), SN65DSI83_CLK_N (bidir), SN65DSI83_CLK_P (bidir), SN65DSI83_D0_N (bidir), SN65DSI83_D0_P (bidir), SN65DSI83_D1_N (bidir), SN65DSI83_D1_P (bidir), SN65DSI83_D2_N (bidir), SN65DSI83_D2_P (bidir), SN65DSI83_D3_N (bidir), SN65DSI83_D3_P (bidir), SN65DSI83_EN (bidir), SN65DSI83_IRQ (bidir), SN65DSI83_SCL (bidir), SN65DSI83_SDA (bidir)

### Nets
1V8_SOM_EXT: C108.2 C109.2 C112.2 C113.2 C114.2 C115.2 C116.2 C117.2 C118.2 C119.2 C120.2 C121.2 C122.2 C123.2 R245.2 U21.3(VCC) U21.14(VCC) U21.18(VCC) U21.32(VCC) U21.35(VCC) U21.40(VCC) U21.43(VCC) U21.48(VCC) U21.49(VCC) U21.55(VCC) U21.58(VCC) U21.63(VCC)
3V3_SOM_EXT: J32.1 R244.1
5V: L17.1
GND: C108.1 C109.1 C110.2 C111.1 C112.1 C113.1 C114.1 C115.1 C116.1 C117.1 C118.1 C119.1 C120.1 C121.1 C122.1 C123.1 J32.4 J32.7 J32.10 J32.13 R242.2 R243.1 R246.1 U21.23(GND) U21.26(GND) U21.52(GND) U21.65(EPAD)
ADDR: R245.1 R246.2 U21.64(ADDR)
LVDS_CLK_N: L15.1 U21.39(A_CLKN)
LVDS_CLK_P: L15.4 U21.38(A_CLKP)
LVDS_I2C_SCL: J32.17 ; port LVDS_I2C_SCL
LVDS_I2C_SDA: J32.18 ; port LVDS_I2C_SDA
LVDS_IRQ_N: J32.19 R244.2 ; port LVDS_IRQ_N
LVDS_PWM_OUT: J32.16 ; port LVDS_PWM_OUT
LVDS_TX0_N: L12.1 U21.47(A_Y0N)
LVDS_TX0_P: L12.4 U21.46(A_Y0P)
LVDS_TX1_N: L13.1 U21.45(A_Y1N)
LVDS_TX1_P: L13.4 U21.44(A_Y1P)
LVDS_TX2_N: L14.1 U21.42(A_Y2N)
LVDS_TX2_P: L14.4 U21.41(A_Y2P)
LVDS_TX3_N: L16.1 U21.37(A_Y3N)
LVDS_TX3_P: L16.4 U21.36(A_Y3P)
SN65DSI83_CLK_N: U21.25(DACN) ; port SN65DSI83_CLK_N
SN65DSI83_CLK_P: U21.24(DACP) ; port SN65DSI83_CLK_P
SN65DSI83_D0_N: U21.20(DA0N) ; port SN65DSI83_D0_N
SN65DSI83_D0_P: U21.19(DA0P) ; port SN65DSI83_D0_P
SN65DSI83_D1_N: U21.22(DA1N) ; port SN65DSI83_D1_N
SN65DSI83_D1_P: U21.21(DA1P) ; port SN65DSI83_D1_P
SN65DSI83_D2_N: U21.28(DA2N) ; port SN65DSI83_D2_N
SN65DSI83_D2_P: U21.27(DA2P) ; port SN65DSI83_D2_P
SN65DSI83_D3_N: U21.30(DA3N) ; port SN65DSI83_D3_N
SN65DSI83_D3_P: U21.29(DA3P) ; port SN65DSI83_D3_P
SN65DSI83_EN: R243.2 U21.2(EN) ; port SN65DSI83_EN
SN65DSI83_IRQ: U21.33(IRQ) ; port SN65DSI83_IRQ
SN65DSI83_SCL: U21.15(SCL) ; port SN65DSI83_SCL
SN65DSI83_SDA: U21.16(SDA) ; port SN65DSI83_SDA
NetC110_1: C110.1 C111.2 U21.31(VCORE)
NetJ32_2: J32.2 L12.2
NetJ32_3: J32.3 L12.3
NetJ32_5: J32.5 L13.2
NetJ32_6: J32.6 L13.3
NetJ32_8: J32.8 L14.2
NetJ32_9: J32.9 L14.3
NetJ32_11: J32.11 L15.2
NetJ32_12: J32.12 L15.3
NetJ32_14: J32.14 L16.2
NetJ32_15: J32.15 L16.3
NetJ32_20: J32.20 L17.2
NetR242_1: R242.1 U21.17(REFCLK)

Not connected (* = marked no-connect by the designer): U21 1(RSVD2)* 4(RSVD)* 5(RSVD)* 6(RSVD)* 7(RSVD)* 8(RSVD)* 9(RSVD)* 10(RSVD)* 11(RSVD)* 12(RSVD)* 13(RSVD)* 34(RSVD1)* 50(RSVD)* 51(RSVD)* 53(RSVD)* 54(RSVD)* 56(RSVD)* 57(RSVD)* 59(RSVD)* 60(RSVD)* 61(RSVD)* 62(RSVD)*

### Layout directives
differential pair; net class DIFF100: LVDS_CLK_N, LVDS_CLK_P, LVDS_TX0_N, LVDS_TX0_P, LVDS_TX1_N, LVDS_TX1_P, LVDS_TX2_N, LVDS_TX2_P, LVDS_TX3_N, LVDS_TX3_P

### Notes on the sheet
- Place one cap close to each of the VCC pins of the SN65DSI83 chip.

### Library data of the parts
C108 = 1001168: as C82 on sheet 13 - MIPI to HDMI bridge
C109 C111 = 1001167: CAP CER 1UF 10V 10% X5R 0402; Part_Type: Capacitor; Manufacturer: Murata; Manufacturer_Part_Number: GRM155R61A105KE15D; Digi_PN: 14050399; Component_Life_Cycle_State: Reviewed; Area: 0.95; Project: CCWMX6_SBC board
C110 C112-C123 = 1000006: as C83 on sheet 13 - MIPI to HDMI bridge
J32 = 1001132: CONN HEADER 20POS 1.25MM R/A SMD; Part_Type: Connector; Manufacturer: Hirose; Digi_PN: 18050231; Component_Life_Cycle_State: Reviewed; Area: 206.34; Project: CCWMX6_SBC board
L12-L16 = 1001014: as L8 on sheet 13 - MIPI to HDMI bridge
L17 = 1001174: FERRITE BEAD 220 OHM 2.0A 0805; Manufacturer: Wurth Electronics Inc; Manufacturer_Part_Number: 742792022; Digi_PN: 21000146; Component_Life_Cycle_State: Reviewed; Area: 4.24; Project: CCWMX6_SBC board
R242 R245 R246 = 1000038: RES 4.7K OHM 1/10W 5% 0402 SMD; Part_Type: Resistor; Manufacturer: Panasonic - ECG; Manufacturer_Part_Number: ERJ-2GEJ472X; Digi_PN: 13050549; Component_Life_Cycle_State: Proven; Area: 0,95; Project: Adjustable Foundation; Power_WV_SRF: 100; Tolerance: 5
R243 R244 = 1000537: as R225 on sheet 13 - MIPI to HDMI bridge
U21 = 1002718: IC BRIDGE DSI TO LVDS 64HTQFP; Manufacturer: Texas Instruments; Digi_PN: 16000196; Component_Life_Cycle_State: Pending; Area: 180,9

## Sheet 15 - USB HUB.SchDoc: USB HUB
size A3; PageSetup: Record=PageOptions¦CenterHorizontal=True¦CenterVertical=True¦PrintScale=0.70¦XCorrection=1.00¦YCorrection=1.00¦PrintKind=0¦BorderSize=5000000¦LeftOffset=0¦BottomOffset=0¦Orientation=2¦PaperLength=4200¦PaperWidth=2970¦Scale=100¦PaperSource=7¦PrintQuality=600¦MediaType=1¦DitherType=10¦PaperKind=A4¦PrintScaleMode=1; Author: Juan Anzola; SheetNumber: 15; SheetTotal: 21
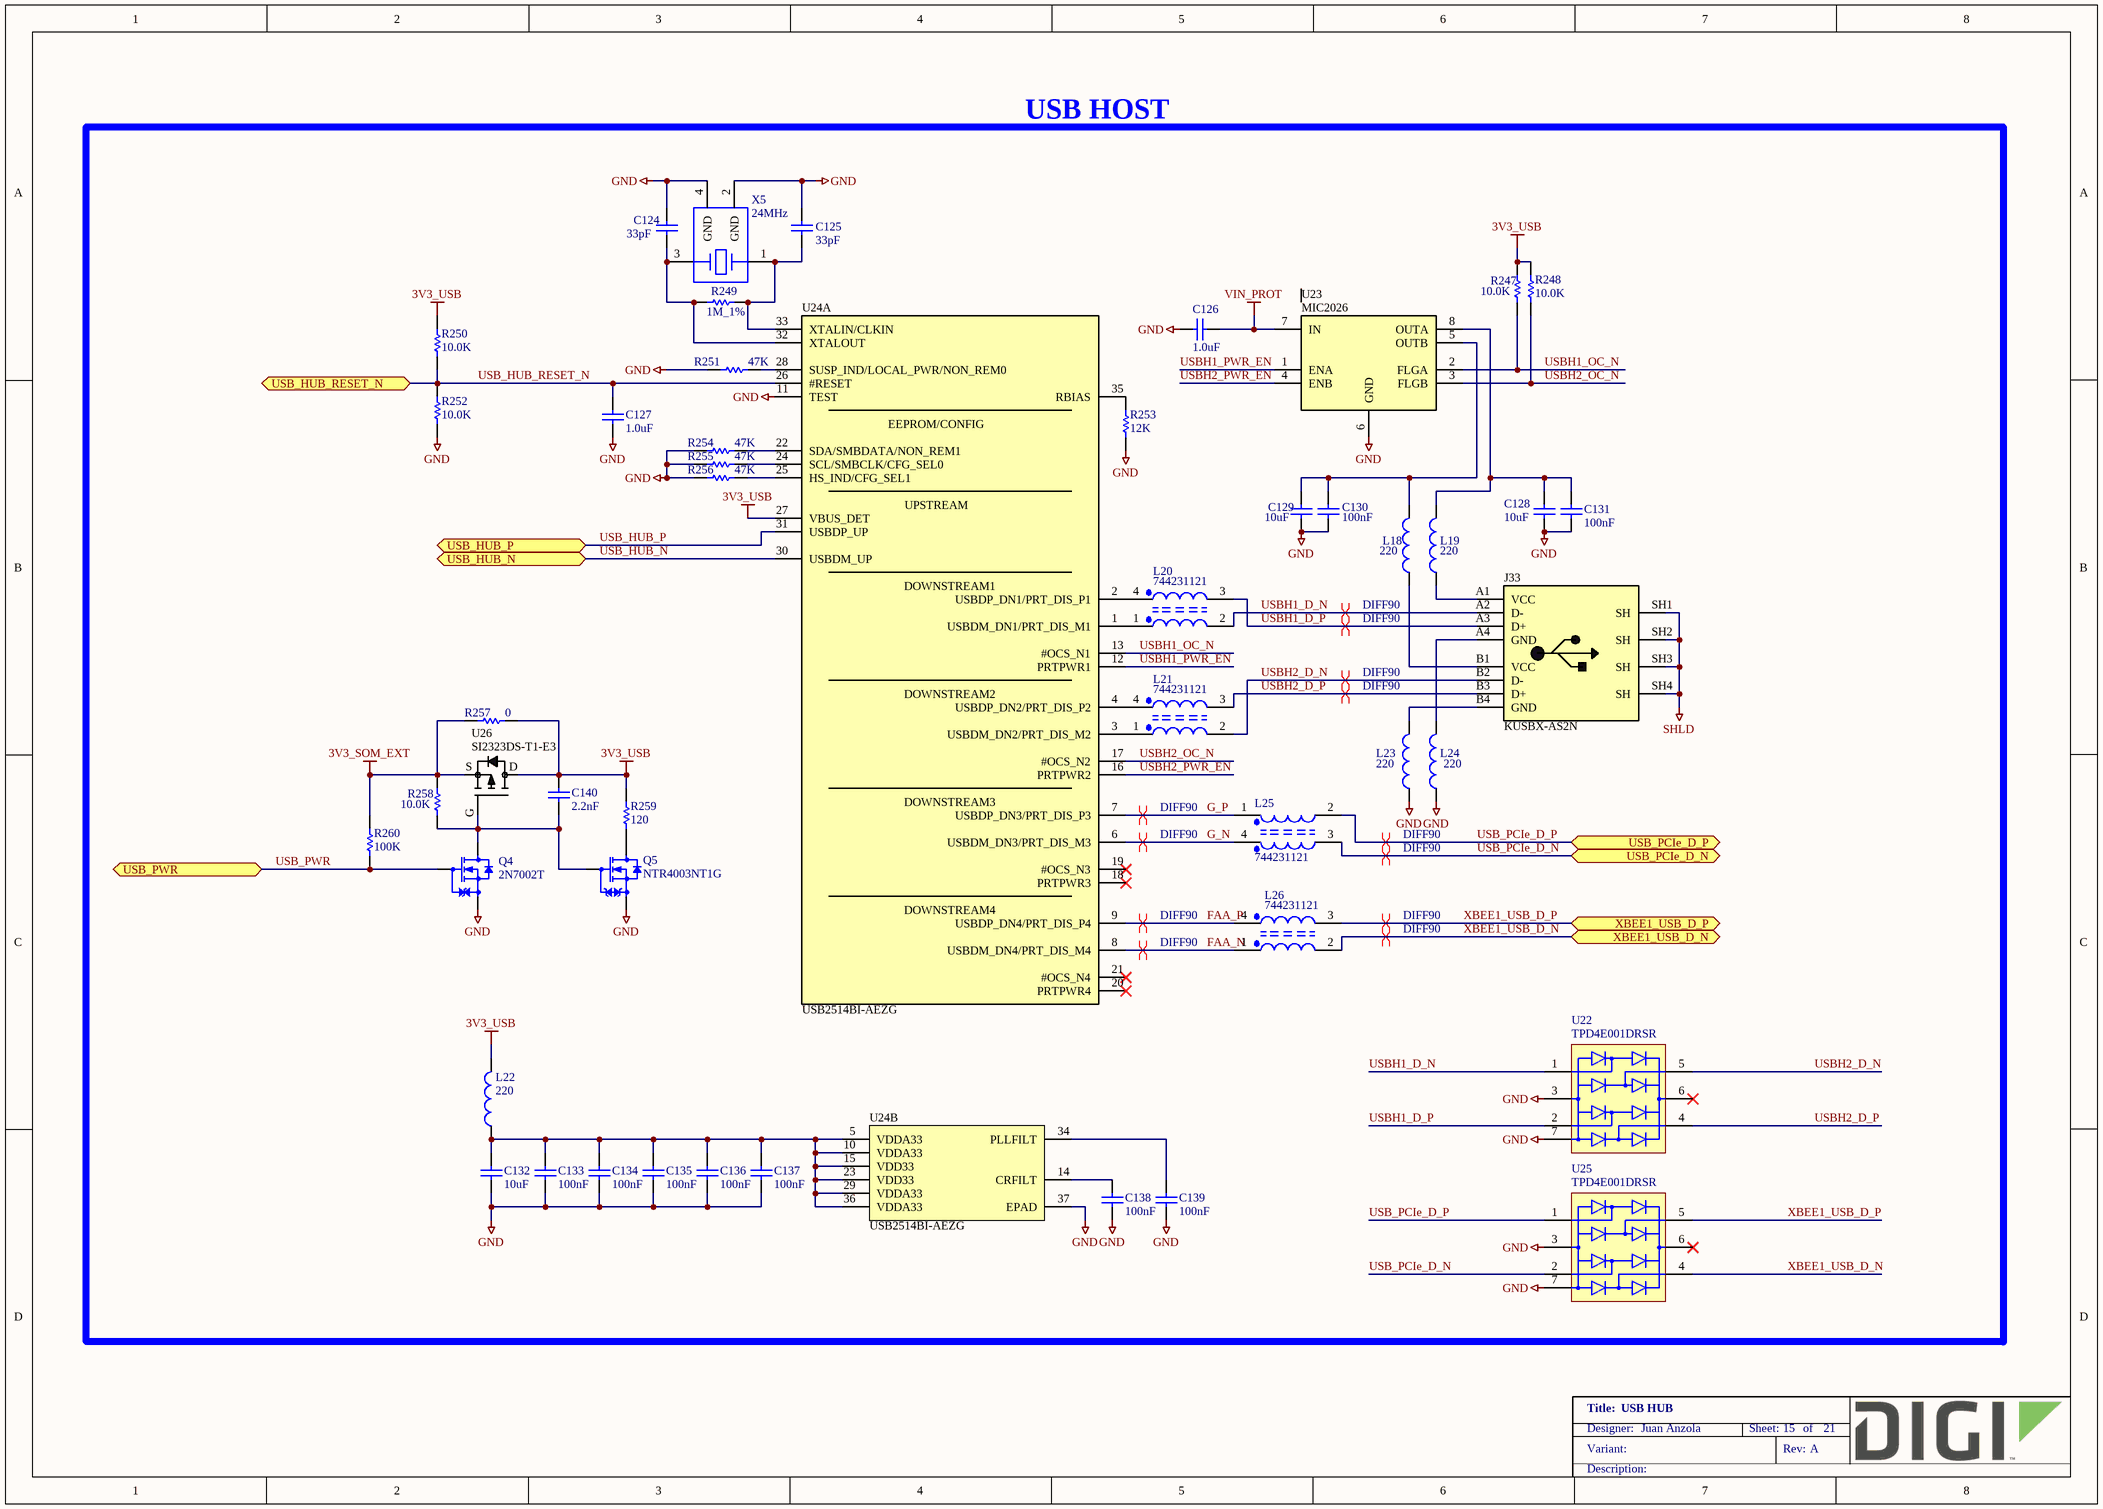
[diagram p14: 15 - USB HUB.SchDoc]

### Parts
C124  33pF  [CAPC1005X55N]
C125  33pF  [CAPC1005X55N]
C126  1.0uF  [CAPC1005X55N]
C127  1.0uF  [CAPC1005X55N]
C128  10uF  [CAPC1005X55N]
C129  10uF  [CAPC1005X55N]
C130  100nF  [CAPC1005X55N]
C131  100nF  [CAPC1005X55N]
C132  10uF  [CAPC1005X55N]
C133  100nF  [CAPC1005X55N]
C134  100nF  [CAPC1005X55N]
C135  100nF  [CAPC1005X55N]
C136  100nF  [CAPC1005X55N]
C137  100nF  [CAPC1005X55N]
C138  100nF  [CAPC1005X55N]
C139  100nF  [CAPC1005X55N]
C140  2.2nF  [CAPC1608X90N]
J33  KUSBX-AS2N  [KYCON_KUSBX-AS2N_Flex]
L18  220  [INDC2013X110N]
L19  220  [INDC2013X110N]
L20  744231121  [FIL_DLW21H]
L21  744231121  [FIL_DLW21H]
L22  220  [INDC2013X110N]
L23  220  [INDC2013X110N]
L24  220  [INDC2013X110N]
L25  744231121  [FIL_DLW21H]
L26  744231121  [FIL_DLW21H]
Q4  2N7002T  [SOTFL50P160X80_GSD-3N]
Q5  NTR4003NT1G  [SOT95P240X110_GSD-3N]
R247  10.0K  [RESC1005X40N]
R248  10.0K  [RESC1005X40N]
R249  1M_1%  [RESC1005X40N]
R250  10.0K  [RESC1005X40N]
R251  47K  [RESC1005X40N]
R252  10.0K  [RESC1005X40N]
R253  12K  [RESC1609X55N]
R254  47K  [RESC1005X40N]
R255  47K  [RESC1005X40N]
R256  47K  [RESC1005X40N]
R257  0  [RESC1609X55N]
R258  10.0K  [RESC1005X40N]
R259  120  [RESC1005X40N]
R260  100K  [RESC1005X40N]
U22  TPD4E001DRSR  [SON95P300X300X80-7N]
U23  MIC2026  [SOIC127P600X175-8N]
U24  USB2514BI-AEZG  [QFN50P600X600X100-37AN]  (parts A,B of 2)
U25  TPD4E001DRSR  [SON95P300X300X80-7N]
U26  SI2323DS-T1-E3  [SOT95P240X110_GSD-3N]
X5  24MHz  [XTAL_C3E-3427]

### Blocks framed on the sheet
USB HOST: C124-C140 J33 L18-L26 Q4 Q5 R247-R260 U22-U26 X5

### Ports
USB_HUB_N (bidir), USB_HUB_P (bidir), USB_HUB_RESET_N (bidir), USB_PCIe_D_N (bidir), USB_PCIe_D_P (bidir), USB_PWR (bidir), XBEE1_USB_D_N (bidir), XBEE1_USB_D_P (bidir)

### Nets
3V3_SOM_EXT: R257.1 R258.1 R260.1 U26.S
3V3_USB: C140.2 L22.2 R247.2 R248.2 R250.2 R257.2 R259.1 U24.27(VBUS_DET) U26.D
GND: C124.2 C125.2 C126.2 C127.1 C128.1 C129.1 C130.1 C131.1 C132.1 C133.1 C134.1 C135.1 C136.1 C137.1 C138.1 C139.1 L23.1 L24.1 Q4.S Q5.S R251.2 R252.1 R253.1 R254.1 R255.1 R256.1 U22.3(GND) U22.7(GND) U23.6(GND) U24.11(TEST) U24.37(EPAD) U25.3(GND) U25.7(GND) X5.2(GND) X5.4(GND)
SHLD: J33.SH1(SH) J33.SH2(SH) J33.SH3(SH) J33.SH4(SH)
VIN_PROT: C126.1 U23.7(IN)
FAA_N: L26.1 U24.8(USBDM_DN4/PRT_DIS_M4)
FAA_P: L26.4 U24.9(USBDP_DN4/PRT_DIS_P4)
G_N: L25.4 U24.6(USBDM_DN3/PRT_DIS_M3)
G_P: L25.1 U24.7(USBDP_DN3/PRT_DIS_P3)
USB_HUB_N: U24.30(USBDM_UP) ; port USB_HUB_N
USB_HUB_P: U24.31(USBDP_UP) ; port USB_HUB_P
USB_HUB_RESET_N: C127.2 R250.1 R252.2 U24.26(#RESET) ; port USB_HUB_RESET_N
USB_PCIe_D_N: L25.3 U25.2(I/O) ; port USB_PCIe_D_N
USB_PCIe_D_P: L25.2 U25.1(I/O) ; port USB_PCIe_D_P
USB_PWR: Q4.G R260.2 ; port USB_PWR
USBH1_D_N: J33.A2(D-) L20.2 U22.1(I/O)
USBH1_D_P: J33.A3(D+) L20.3 U22.2(I/O)
USBH1_OC_N: R247.1 U23.2(FLGA) U24.13(#OCS_N1)
USBH1_PWR_EN: U23.1(ENA) U24.12(PRTPWR1)
USBH2_D_N: J33.B2(D-) L21.2 U22.5(I/O)
USBH2_D_P: J33.B3(D+) L21.3 U22.4(I/O)
USBH2_OC_N: R248.1 U23.3(FLGB) U24.17(#OCS_N2)
USBH2_PWR_EN: U23.4(ENB) U24.16(PRTPWR2)
XBEE1_USB_D_N: L26.2 U25.4(I/O) ; port XBEE1_USB_D_N
XBEE1_USB_D_P: L26.3 U25.5(I/O) ; port XBEE1_USB_D_P
NetC124_1: C124.1 R249.1 U24.32(XTALOUT) X5.3
NetC125_1: C125.1 R249.2 U24.33(XTALIN/CLKIN) X5.1
NetC128_2: C128.2 C131.2 L19.2 U23.8(OUTA)
NetC129_2: C129.2 C130.2 L18.2 U23.5(OUTB)
NetC132_2: C132.2 C133.2 C134.2 C135.2 C136.2 C137.2 L22.1 U24.5(VDDA33) U24.10(VDDA33) U24.15(VDD33) U24.23(VDD33) U24.29(VDDA33) U24.36(VDDA33)
NetC138_2: C138.2 U24.14(CRFILT)
NetC139_2: C139.2 U24.34(PLLFILT)
NetC140_1: C140.1 Q4.D Q5.G R258.2 U26.G
NetJ33_A1: J33.A1(VCC) L19.1
NetJ33_A4: J33.A4(GND) L24.2
NetJ33_B1: J33.B1(VCC) L18.1
NetJ33_B4: J33.B4(GND) L23.2
NetL20_1: L20.1 U24.1(USBDM_DN1/PRT_DIS_M1)
NetL20_4: L20.4 U24.2(USBDP_DN1/PRT_DIS_P1)
NetL21_1: L21.1 U24.3(USBDM_DN2/PRT_DIS_M2)
NetL21_4: L21.4 U24.4(USBDP_DN2/PRT_DIS_P2)
NetQ5_D: Q5.D R259.2
NetR251_1: R251.1 U24.28(SUSP_IND/LOCAL_PWR/NON_REM0)
NetR253_2: R253.2 U24.35(RBIAS)
NetR254_2: R254.2 U24.22(SDA/SMBDATA/NON_REM1)
NetR255_2: R255.2 U24.24(SCL/SMBCLK/CFG_SEL0)
NetR256_2: R256.2 U24.25(HS_IND/CFG_SEL1)

Not connected (* = marked no-connect by the designer): U22 6(VCC)*; U24 18(PRTPWR3)* 19(#OCS_N3)* 20(PRTPWR4)* 21(#OCS_N4)*; U25 6(VCC)*

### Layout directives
differential pair; net class DIFF90: FAA_N, FAA_P, G_N, G_P, USB_PCIe_D_N, USB_PCIe_D_P, USBH1_D_N, USBH1_D_P, USBH2_D_N, USBH2_D_P, XBEE1_USB_D_N, XBEE1_USB_D_P

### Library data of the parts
C124 C125 = 1002646: CAP CER 33PF 50V C0G/NP0 0402; Part_Type: Capacitor; Manufacturer: Murata; Manufacturer_Part_Number: GCM1555C1H330JA16D; Digi_PN: 14050400; Component_Life_Cycle_State: Reviewed; Area: 2,12; Voltage: 50; Tolerance: 5%
C126 C127 = 1001167: as C109 on sheet 14 - MIPI to LVDS bridge
C128 C129 C132 = 1001168: as C82 on sheet 13 - MIPI to HDMI bridge
C130 C131 C133-C139 = 1000006: as C83 on sheet 13 - MIPI to HDMI bridge
C140 = 1002727: as C87 on sheet 13 - MIPI to HDMI bridge
J33 = 1001121: USB Stacked Dual A type; Part_Type: Connector; Manufacturer: KYCON; Digi_PN: 18000276; Component_Life_Cycle_State: Reviewed; Area: 164; Project: CCWMX6_SBC board
L18 L19 L22-L24 = 1001174: as L17 on sheet 14 - MIPI to LVDS bridge
L20 L21 L25 L26 = 1001173: CHOKE COM MODE 120 OHM .37A; Part_Type: Inductor; Manufacturer: Wurth Electronics Inc; Digi_PN: 21000143; Component_Life_Cycle_State: Reviewed; Area: 2.4; Project: CCWMX6_SBC board
Q4 = 1000715: MOSFET N-CH 60V 115MA SOT-523F; Part_Type: Transistor; Manufacturer: Fairchild Semiconductor; Digi_PN: 17050797; Component_Life_Cycle_State: CAD Reviewed; Area: 3.06; Project: SmartMeter2; Note: 17050841 = Digi No. for GE WDNU
Q5 = 1000306: MOSFET N-CH 30V 500MA SOT-23; Part_Type: Transistor; Manufacturer: On Semiconductor; Digi_PN: 17050809; Component_Life_Cycle_State: Proven; Area: 10,92; Project: Adjustable Foundation
R247 R248 R250 R252 R258 = 1000537: as R225 on sheet 13 - MIPI to HDMI bridge
R249 = 1000971: RES 1.00M OHM 1/16W 1% 0402 SMD; Part_Type: Resistor; Manufacturer: Yageo; Manufacturer_Part_Number: RC0402FR-071ML; Digi_PN: 13050561; Component_Life_Cycle_State: Reviewed; Area: 0.95; Project: ConnectCore i.MX6 module; Power_WV_SRF: 63; Tolerance: 1; Note: 13051098 = Digi No. for GE WDNU
R251 R254-R256 = 1001155: as R231 on sheet 13 - MIPI to HDMI bridge
R253 = 1001200: RES 12.0K OHM 1/10W 1% 0603 SMD; Part_Type: Resistor; Manufacturer: Yageo; Manufacturer_Part_Number: RC0603FR-0712KL; Digi_PN: 13050531; Component_Life_Cycle_State: Reviewed; Area: 2.5; Project: LuCoV2; Power_WV_SRF: 100; Tolerance: 1
R257 = 1000208: RES 0.0 OHM 1/10W 0603; Part_Type: Resistor; Manufacturer: Panasonic - ECG; Manufacturer_Part_Number: ERJ-3GEY0R00V; Note: 13051103 = Digi No. for GE WDNU; Digi_PN: 13050568; Component_Life_Cycle_State: Reviewed; Area: 2.5; Project: Adjustable Foundation; Voltage: 75V
R259 = 1001158: RES 120 OHM 1/16W 1% 0402 SMD; Part_Type: Resistor; Manufacturer: Yageo; Manufacturer_Part_Number: RC0402FR-07120RL; Digi_PN: 13050832; Component_Life_Cycle_State: Reviewed; Area: 0.95; Project: CCWMX6_SBC board; Note: 13051102 = Digi No. for GE WDNU
R260 = 1000480: RES 100K OHM 1/10W 1% 0402 SMD; Part_Type: Resistor; Manufacturer: Panasonic - ECG; Manufacturer_Part_Number: ERJ-2RKF1003X; Digi_PN: 13051063; Component_Life_Cycle_State: CAD Reviewed; Area: 0.95; Project: KITT; Power_WV_SRF: 100
U22 U25 = 1001265: TVS DIODE 5.5VWM 6SON; Part_Type: IC; Manufacturer: Texas Instruments; Digi_PN: 17050690; Component_Life_Cycle_State: Reviewed; Area: 10; Project: CCWMX6_SBC board; Note: 17050839 = Digi No. for GE WDNU
U23 = 1001143: IC SW DISTRIBUTION 2CHAN 8SOIC; Manufacturer: Micrel; Manufacturer_Part_Number: MIC2026-1YM; Digi_PN: 16051879; Component_Life_Cycle_State: Reviewed; Area: 29.58; Project: CCWMX6_SBC board
U24 = 1001114: 4-PORT USB 2.0 HUB CTRLR 36VQFN; Part_Type: IC; Manufacturer: SMSC; Digi_PN: 16051280; Component_Life_Cycle_State: Reviewed; Area: 36; Project: CCWMX6_SBC board
U26 = 1001163: MOSFET P-CH 20V 3.7A SOT23-3; Part_Type: IC; Manufacturer: Vishay Siliconix; Digi_PN: 17050358; Component_Life_Cycle_State: Reviewed; Area: 10.92; Project: CCWMX6_SBC board
X5 = 1001134: CRYSTAL 24MHZ 18PF SMD; Part_Type: Crystals-Oscillators; Manufacturer: Aker; Manufacturer_Part_Number: C3E-24.000-18-3030-X-R; Digi_PN: 20000223; Component_Life_Cycle_State: Reviewed; Area: 9.18; Project: CCWMX6_SBC board

## Sheet 16 - USB Recovery, USB OTG.SchDoc: USB Recovery, USB OTG
size A3; PageSetup: Record=PageOptions¦CenterHorizontal=True¦CenterVertical=True¦PrintScale=0.70¦XCorrection=1.00¦YCorrection=1.00¦PrintKind=0¦BorderSize=5000000¦LeftOffset=0¦BottomOffset=0¦Orientation=2¦PaperLength=4200¦PaperWidth=2970¦Scale=100¦PaperSource=7¦PrintQuality=600¦MediaType=1¦DitherType=10¦PaperKind=A4¦PrintScaleMode=1; Author: Juan Anzola; SheetNumber: 16; SheetTotal: 21
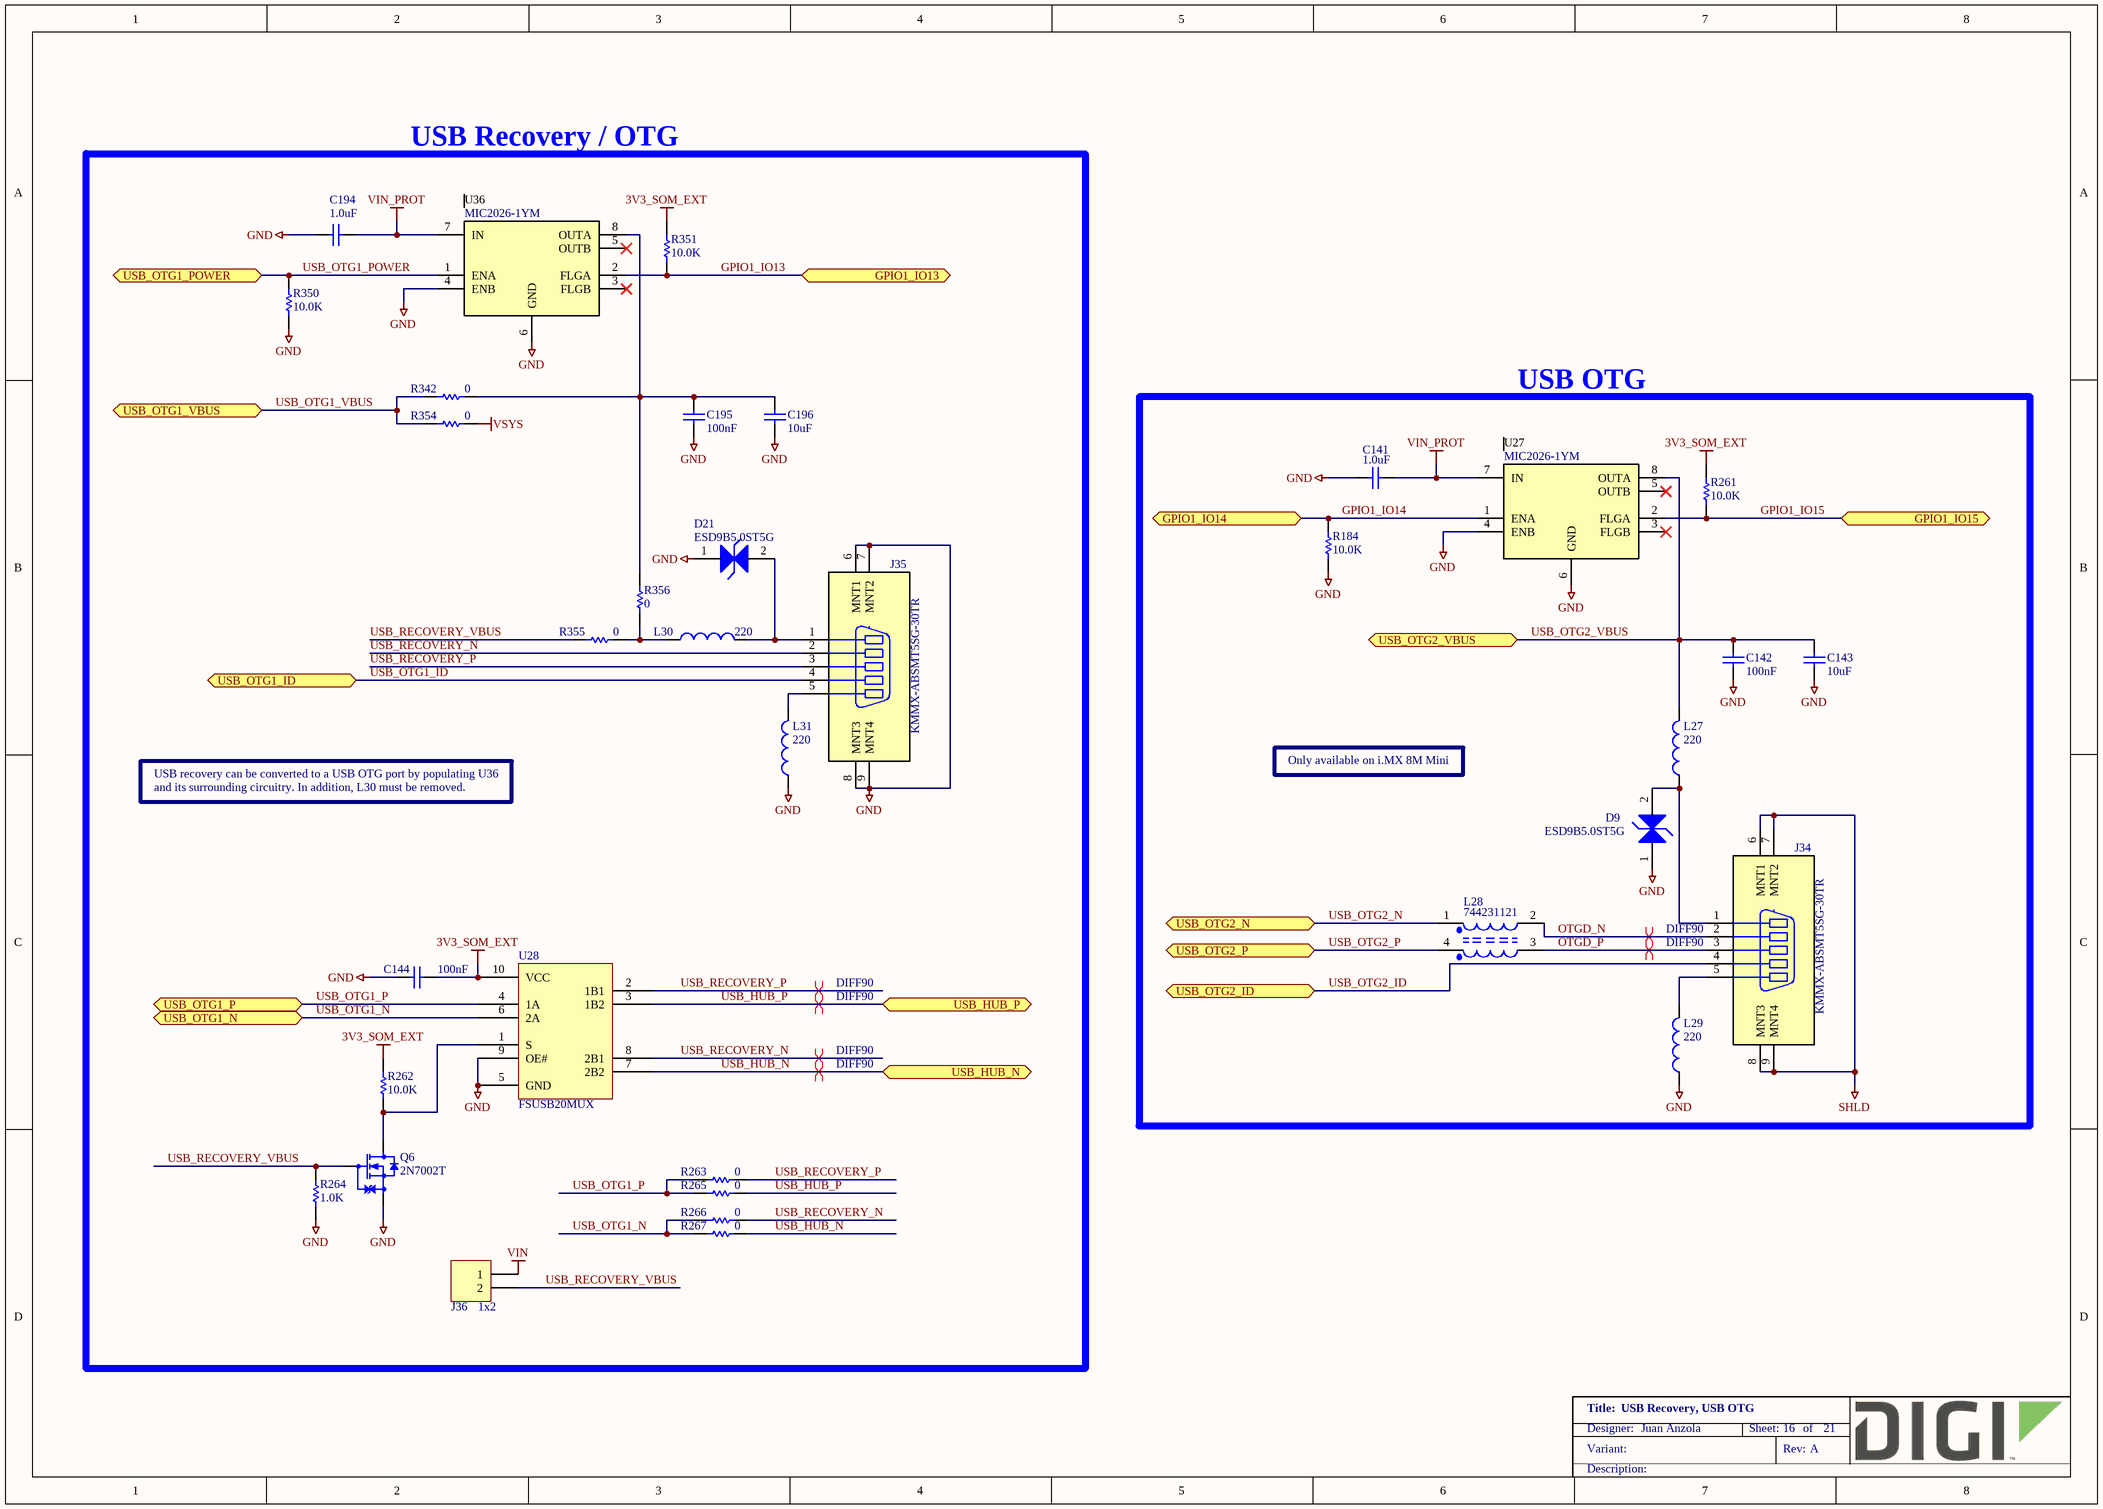
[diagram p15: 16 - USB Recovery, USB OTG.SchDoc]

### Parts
C141  1.0uF  [CAPC1005X55N]
C142  100nF  [CAPC1005X55N]
C143  10uF  [CAPC1005X55N]
C144  100nF  [CAPC1005X55N]
C194  1.0uF  [CAPC1005X55N]
C195  100nF  [CAPC1005X55N]
C196  10uF  [CAPC1005X55N]
D9  ESD9B5.0ST5G  [SODFL1006X43N12]
D21  ESD9B5.0ST5G  [SODFL1006X43N12]
J34  KMMX-ABSMT5SG-30TR  [KYCON_KMMX-ABSMT5]
J35  KMMX-ABSMT5SG-30TR  [KYCON_KMMX-ABSMT5]
J36  1x2  [FCI_68002-102HLF]
L27  220  [INDC2013X110N]
L28  744231121  [FIL_DLW21H]
L29  220  [INDC2013X110N]
L30  220  [INDC2013X110N]
L31  220  [INDC2013X110N]
Q6  2N7002T  [SOTFL50P160X80_GSD-3N]
R184  10.0K  [RESC1005X40N]
R261  10.0K  [RESC1005X40N]
R262  10.0K  [RESC1005X40N]
R263  0  [RESC1609X55N]
R264  1.0K  [RESC1005X40N]
R265  0  [RESC1609X55N]
R266  0  [RESC1609X55N]
R267  0  [RESC1609X55N]
R342  0  [RESC1005X40N]
R350  10.0K  [RESC1005X40N]
R351  10.0K  [RESC1005X40N]
R354  0  [RESC1005X40N]
R355  0  [RESC1609X55N]
R356  0  [RESC1609X55N]
U27  Manufacturer_Part_Number: MIC2026-1YM  [SOIC127P600X175-8N]  (hidden comment: MIC2026)
U28  FSUSB20MUX  [SOP50P490X110-10L30N]
U36  Manufacturer_Part_Number: MIC2026-1YM  [SOIC127P600X175-8N]  (hidden comment: MIC2026)

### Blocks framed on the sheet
USB Recovery / OTG: C144 C194-C196 D21 J35 J36 L30 L31 Q6 R262-R267 R342 R350 R351 R354-R356 U28 U36
USB OTG: C141-C143 D9 J34 L27-L29 R184 R261 U27

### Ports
GPIO1_IO13 (bidir), GPIO1_IO14 (bidir), GPIO1_IO15 (bidir), USB_HUB_N (bidir), USB_HUB_P (bidir), USB_OTG1_ID (bidir), USB_OTG1_N (bidir), USB_OTG1_P (bidir), USB_OTG1_POWER (bidir), USB_OTG1_VBUS (bidir), USB_OTG2_ID (bidir), USB_OTG2_N (bidir), USB_OTG2_P (bidir), USB_OTG2_VBUS (bidir)

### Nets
3V3_SOM_EXT: C144.1 R261.2 R262.1 R351.2 U28.10(VCC)
GND: C141.1 C142.1 C143.1 C144.2 C194.1 C195.1 C196.1 D9.1 D21.1 J35.6(MNT1) J35.7(MNT2) J35.8(MNT3) J35.9(MNT4) L29.1 L31.2 Q6.S R184.1 R264.1 R350.1 U27.4(ENB) U27.6(GND) U28.5(GND) U28.9(OE#) U36.4(ENB) U36.6(GND)
SHLD: J34.6(MNT1) J34.7(MNT2) J34.8(MNT3) J34.9(MNT4)
VIN: J36.1
VIN_PROT: C141.2 C194.2 U27.7(IN) U36.7(IN)
VSYS: R354.2
GPIO1_IO13: R351.1 U36.2(FLGA) ; port GPIO1_IO13
GPIO1_IO14: R184.2 U27.1(ENA) ; port GPIO1_IO14
GPIO1_IO15: R261.1 U27.2(FLGA) ; port GPIO1_IO15
OTGD_N: J34.2 L28.2
OTGD_P: J34.3 L28.3
USB_HUB_N: R267.2 U28.7(2B2) ; port USB_HUB_N
USB_HUB_P: R265.2 U28.3(1B2) ; port USB_HUB_P
USB_OTG1_ID: J35.4 ; port USB_OTG1_ID
USB_OTG1_N: R266.1 R267.1 U28.6(2A) ; port USB_OTG1_N
USB_OTG1_P: R263.1 R265.1 U28.4(1A) ; port USB_OTG1_P
USB_OTG1_POWER: R350.2 U36.1(ENA) ; port USB_OTG1_POWER
USB_OTG1_VBUS: R342.1 R354.1 ; port USB_OTG1_VBUS
USB_OTG2_ID: J34.4 ; port USB_OTG2_ID
USB_OTG2_N: L28.1 ; port USB_OTG2_N
USB_OTG2_P: L28.4 ; port USB_OTG2_P
USB_OTG2_VBUS: C142.2 C143.2 L27.2 U27.8(OUTA) ; port USB_OTG2_VBUS
USB_RECOVERY_N: J35.2 R266.2 U28.8(2B1)
USB_RECOVERY_P: J35.3 R263.2 U28.2(1B1)
USB_RECOVERY_VBUS: J36.2 Q6.G R264.2 R355.1
NetC195_2: C195.2 C196.2 R342.2 R356.2 U36.8(OUTA)
NetD9_2: D9.2 J34.1 L27.1
NetD21_2: D21.2 J35.1 L30.1
NetJ34_5: J34.5 L29.2
NetJ35_5: J35.5 L31.1
NetL30_2: L30.2 R355.2 R356.1
NetQ6_D: Q6.D R262.2 U28.1(S)

Not connected (* = marked no-connect by the designer): U27 3(FLGB)* 5(OUTB)*; U36 3(FLGB)* 5(OUTB)*

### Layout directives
differential pair; net class DIFF90: OTGD_N, OTGD_P, USB_HUB_N, USB_HUB_P, USB_RECOVERY_N, USB_RECOVERY_P

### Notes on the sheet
- USB recovery can be converted to a USB OTG port by populating U36
- Only available on i.MX 8M Mini
- and its surrounding circuitry. In addition, L30 must be removed.

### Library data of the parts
C141 = 1001167: as C109 on sheet 14 - MIPI to LVDS bridge
C142 C144 = 1000006: as C83 on sheet 13 - MIPI to HDMI bridge
C143 = 1001168: as C82 on sheet 13 - MIPI to HDMI bridge
C194 = 1001167: CAP CER 1UF 10V 10% X5R 0402; Part_Type: Capacitor; Manufacturer: Murata; Manufacturer_Part_Number: GRM155R61A105KE15D; Digi_PN: 14050399; Component_Life_Cycle_State: Reviewed; Area: 0,95
C195 = 1000006: CAP 100nF 16V 10% X7R 0402; Part_Type: Capacitor; Manufacturer: Murata; Manufacturer_Part_Number: GRM155R71C104KA88D; Digi_PN: 14050552; Component_Life_Cycle_State: CAD Reviewed; Area: 0,95; Tolerance: 10
C196 = 1001168: CAP CER 10UF 10V 20% X5R 0402; Part_Type: Capacitor; Manufacturer: Samsung; Manufacturer_Part_Number: CL05A106MP5NUNC; Digi_PN: 14050689; Component_Life_Cycle_State: Reviewed; Area: 0,95
D9 D21 = 1001264: TVS DIODE 5VWM SOD923; Part_Type: Diodes; Manufacturer: On Semiconductor; Digi_PN: 17050587; Component_Life_Cycle_State: Reviewed; Area: 1.5; Project: CCWMX6_SBC board
J34 = 1001117: CONN RECEPT MICRO-USB TYPE AB R/A; Part_Type: Connector; Manufacturer: KYCON; Digi_PN: 18000401; Component_Life_Cycle_State: Reviewed; Area: 40; Project: CCWMX6_SBC board
J35 = 1001117: CONN RECEPT MICRO-USB TYPE AB R/A; Part_Type: Connector; Manufacturer: KYCON; Digi_PN: 18000401; Component_Life_Cycle_State: Reviewed; Area: 40
J36 = 1001128: CONN HEADER 2POS .100" SGL GOLD; Part_Type: Connector; Manufacturer: Samtec; Manufacturer_Part_Number: TSW-102-07-G-S; Digi_PN: 00120002; Component_Life_Cycle_State: Reviewed; Area: 12,9032
L27 L29 L30 = 1001174: as L17 on sheet 14 - MIPI to LVDS bridge
L28 = 1001173: as L20 on sheet 15 - USB HUB
L31 = 1001174: FERRITE BEAD 220 OHM 2.0A 0805; Manufacturer: Wurth Electronics Inc; Manufacturer_Part_Number: 742792022; Digi_PN: 21000146; Component_Life_Cycle_State: Reviewed; Area: 4,24
Q6 = 1000715: MOSFET N-CH 60V 115MA SOT-523F; Part_Type: Transistor; Manufacturer: Fairchild Semiconductor; Note: 17050841 = Digi No. for GE WDNU; Digi_PN: 17050797; Component_Life_Cycle_State: CAD Reviewed; Area: 3,06; Project: SmartMeter2
R184 R261 R262 = 1000537: as R225 on sheet 13 - MIPI to HDMI bridge
R263 R265-R267 R355 R356 = 1000208: as R203-R223 on sheet 12 - MIPI display and switch, MIPI camera
R264 = 1000079: RES 1.00K OHM 1/10W 1% 0402 SMD; Part_Type: Resistor; Manufacturer: Panasonic - ECG; Manufacturer_Part_Number: ERJ-2RKF1001X; Digi_PN: 13051085; Component_Life_Cycle_State: Proven; Area: 0,95; Project: Adjustable Foundation; Power_WV_SRF: 10
R342 R354 = 1000076: RES 0.0 OHM 1/10W 0402 SMD; Part_Type: Resistor; Manufacturer: Panasonic - ECG; Manufacturer_Part_Number: ERJ-2GE0R00X; Digi_PN: 13050387; Component_Life_Cycle_State: Proven; Area: 0,95; Power_WV_SRF: 10
R350 R351 = 1000537: as R337 on sheet 12 - MIPI display and switch, MIPI camera
U27 U36 = 1001143: IC SW DISTRIBUTION 2CHAN 8SOIC; Manufacturer: Micrel; Digi_PN: 16051879; Component_Life_Cycle_State: Reviewed; Area: 29.58; Project: CCWMX6_SBC board
U28 = 1002730: IC USB SWITCH DUAL 2X1 10MSOP; Manufacturer: On Semiconductor; Digi_PN: 16051919; Component_Life_Cycle_State: Pending; Area: 17,58

## Sheet 17 - Audio.SchDoc: Audio
size A3; PageSetup: Record=PageOptions¦CenterHorizontal=True¦CenterVertical=True¦PrintScale=0.70¦XCorrection=1.00¦YCorrection=1.00¦PrintKind=0¦BorderSize=5000000¦LeftOffset=0¦BottomOffset=0¦Orientation=2¦PaperLength=4200¦PaperWidth=2970¦Scale=100¦PaperSource=7¦PrintQuality=600¦MediaType=1¦DitherType=10¦PaperKind=A4¦PrintScaleMode=1; Author: Juan Anzola; SheetNumber: 17; SheetTotal: 21
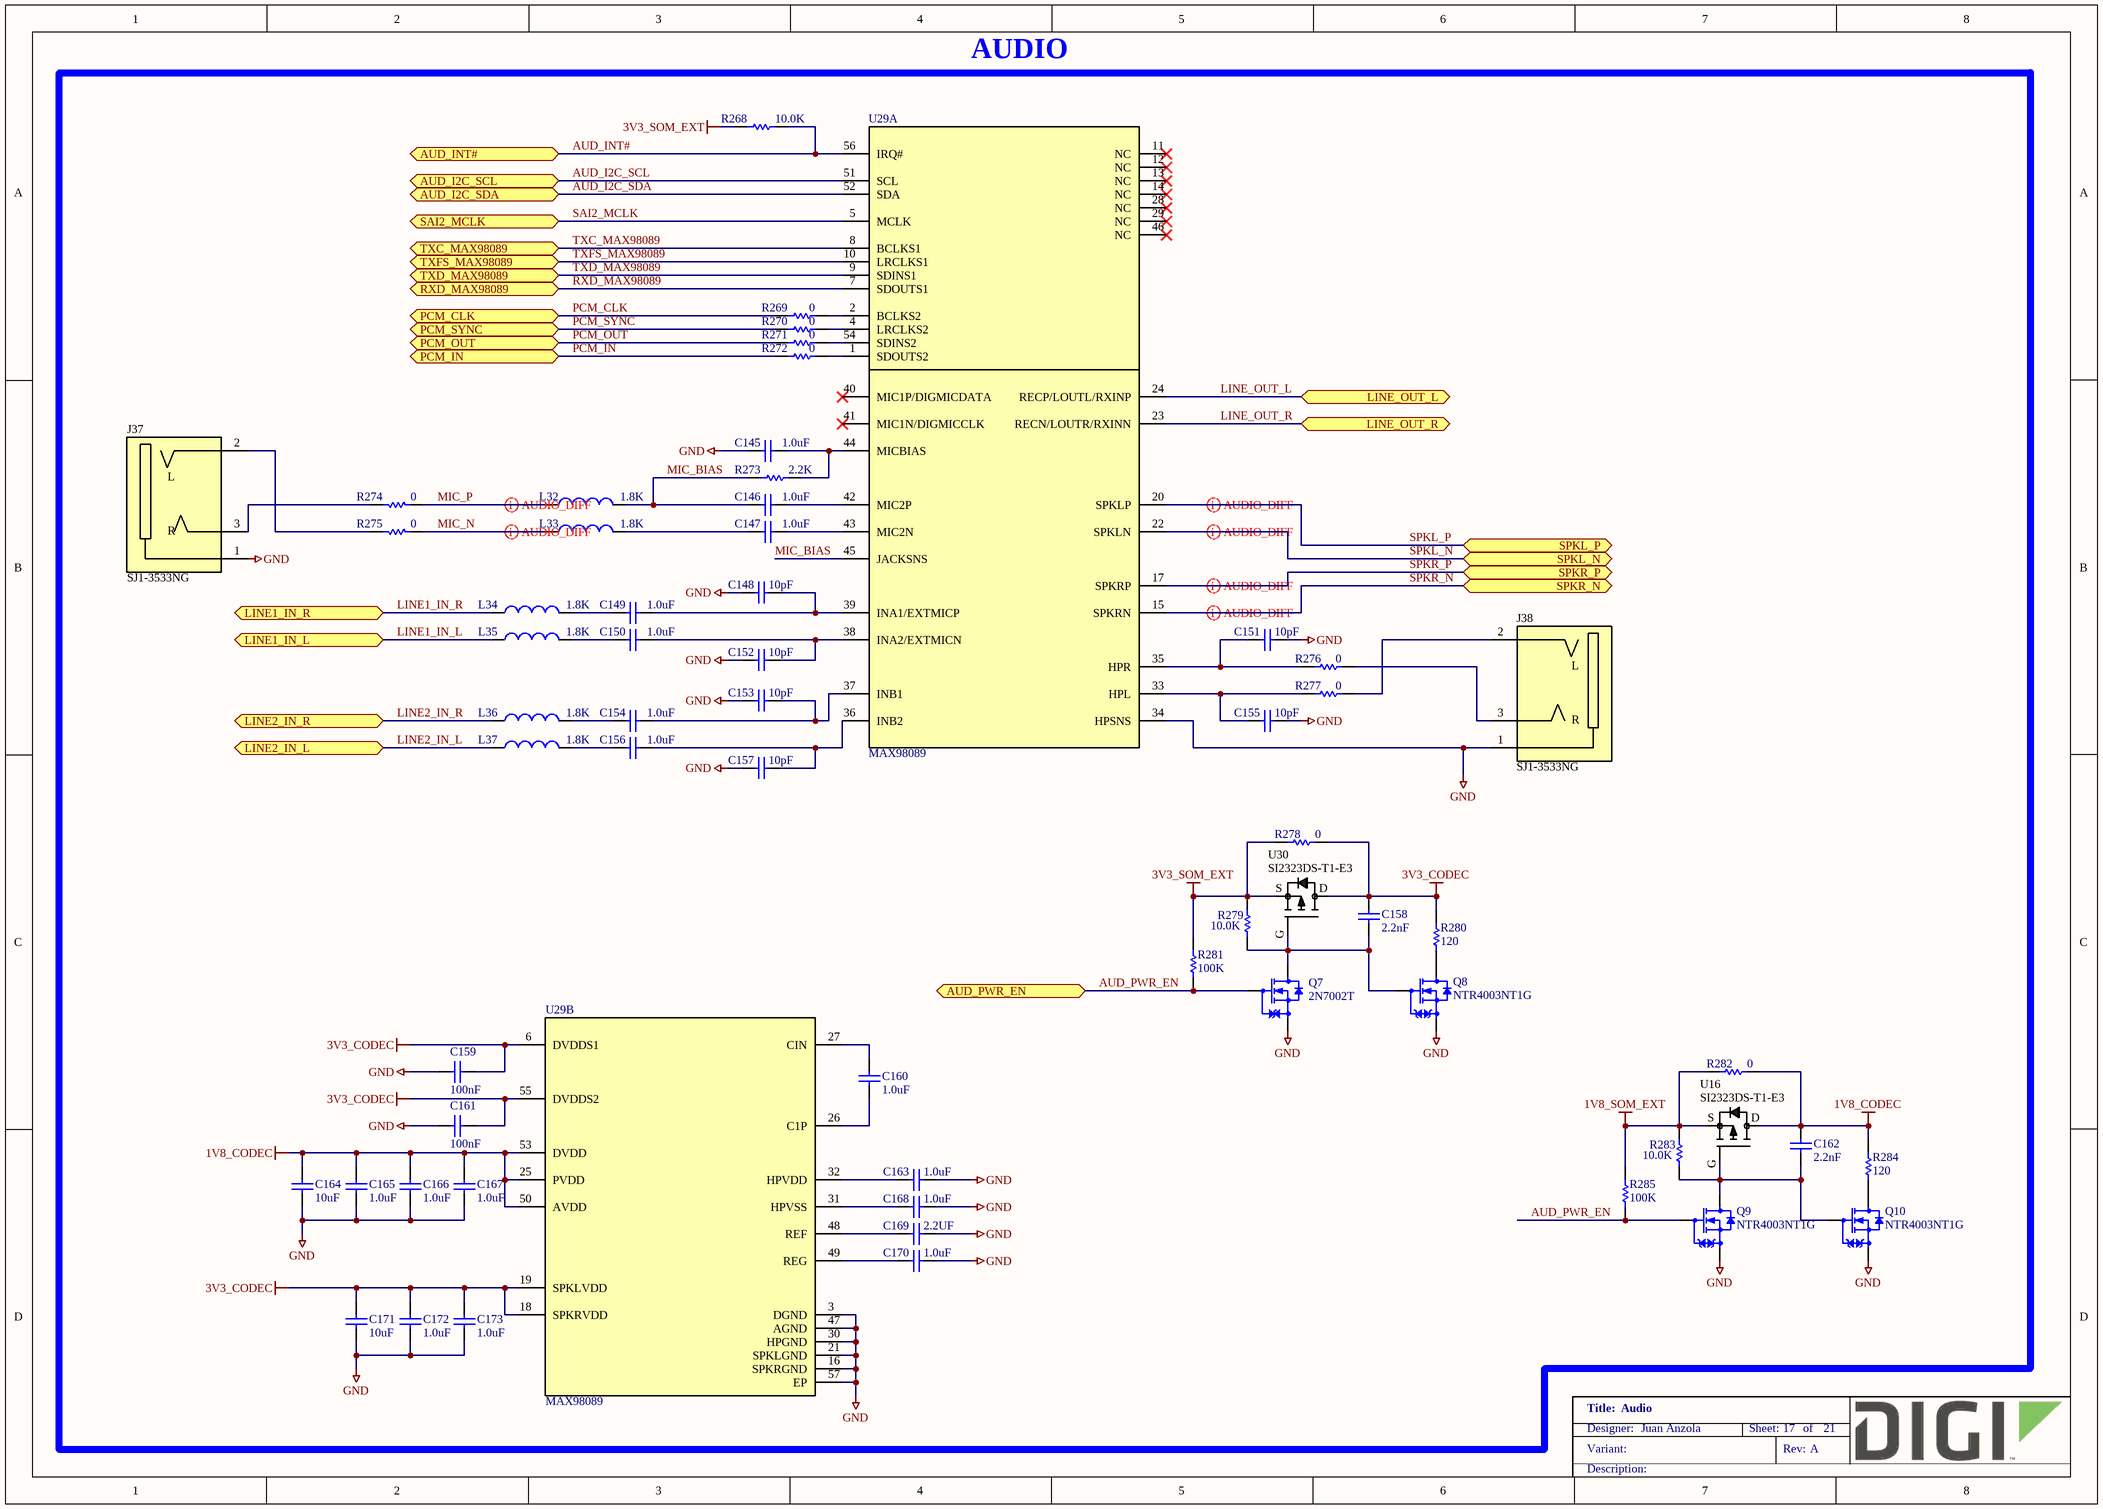
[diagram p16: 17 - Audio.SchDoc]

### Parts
C145  1.0uF  [CAPC1005X55N]
C146  1.0uF  [CAPC1005X55N]
C147  1.0uF  [CAPC1005X55N]
C148  10pF  [CAPC1005X55N]
C149  1.0uF  [CAPC1005X55N]
C150  1.0uF  [CAPC1005X55N]
C151  10pF  [CAPC1005X55N]
C152  10pF  [CAPC1005X55N]
C153  10pF  [CAPC1005X55N]
C154  1.0uF  [CAPC1005X55N]
C155  10pF  [CAPC1005X55N]
C156  1.0uF  [CAPC1005X55N]
C157  10pF  [CAPC1005X55N]
C158  2.2nF  [CAPC1608X90N]
C159  100nF  [CAPC1005X55N]
C160  1.0uF  [CAPC1005X55N]
C161  100nF  [CAPC1005X55N]
C162  2.2nF  [CAPC1608X90N]
C163  1.0uF  [CAPC1005X55N]
C164  10uF  [CAPC1005X55N]
C165  1.0uF  [CAPC1005X55N]
C166  1.0uF  [CAPC1005X55N]
C167  1.0uF  [CAPC1005X55N]
C168  1.0uF  [CAPC1005X55N]
C169  2.2UF  [CAPC1608X90N]
C170  1.0uF  [CAPC1005X55N]
C171  10uF  [CAPC1005X55N]
C172  1.0uF  [CAPC1005X55N]
C173  1.0uF  [CAPC1005X55N]
J37  SJ1-3533NG  [CUI_SJ1-3533N]
J38  SJ1-3533NG  [CUI_SJ1-3533N]
L32  1.8K  [INDC1005X60N]
L33  1.8K  [INDC1005X60N]
L34  1.8K  [INDC1005X60N]
L35  1.8K  [INDC1005X60N]
L36  1.8K  [INDC1005X60N]
L37  1.8K  [INDC1005X60N]
Q7  2N7002T  [SOTFL50P160X80_GSD-3N]
Q8  NTR4003NT1G  [SOT95P240X110_GSD-3N]
Q9  NTR4003NT1G  [SOT95P240X110_GSD-3N]
Q10  NTR4003NT1G  [SOT95P240X110_GSD-3N]
R268  10.0K  [RESC1005X40N]
R269  0  [RESC1005X40N]
R270  0  [RESC1005X40N]
R271  0  [RESC1005X40N]
R272  0  [RESC1005X40N]
R273  2.2K  [RESC1005X40N]
R274  0  [RESC1005X40N]
R275  0  [RESC1005X40N]
R276  0  [RESC1005X40N]
R277  0  [RESC1005X40N]
R278  0  [RESC1609X55N]
R279  10.0K  [RESC1005X40N]
R280  120  [RESC1005X40N]
R281  100K  [RESC1005X40N]
R282  0  [RESC1609X55N]
R283  10.0K  [RESC1005X40N]
R284  120  [RESC1005X40N]
R285  100K  [RESC1005X40N]
U16  SI2323DS-T1-E3  [SOT95P240X110_GSD-3N]
U29  MAX98089  [QFN40P700X700X80-57T560X560N]  (parts A,B of 2)
U30  SI2323DS-T1-E3  [SOT95P240X110_GSD-3N]

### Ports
AUD_I2C_SCL (bidir), AUD_I2C_SDA (bidir), AUD_INT# (bidir), AUD_PWR_EN (bidir), LINE1_IN_L (bidir), LINE1_IN_R (bidir), LINE2_IN_L (bidir), LINE2_IN_R (bidir), LINE_OUT_L (bidir), LINE_OUT_R (bidir), PCM_CLK (bidir), PCM_IN (bidir), PCM_OUT (bidir), PCM_SYNC (bidir), RXD_MAX98089 (bidir), SAI2_MCLK (bidir), SPKL_N (bidir), SPKL_P (bidir), SPKR_N (bidir), SPKR_P (bidir), TXC_MAX98089 (bidir), TXD_MAX98089 (bidir), TXFS_MAX98089 (bidir)

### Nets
1V8_CODEC: C162.2 C164.2 C165.1 C166.1 C167.1 R282.2 R284.1 U16.D U29.25(PVDD) U29.50(AVDD) U29.53(DVDD)
1V8_SOM_EXT: R282.1 R283.1 R285.1 U16.S
3V3_CODEC: C158.2 C159.2 C161.2 C171.2 C172.1 C173.1 R278.2 R280.1 U29.6(DVDDS1) U29.18(SPKRVDD) U29.19(SPKLVDD) U29.55(DVDDS2) U30.D
3V3_SOM_EXT: R268.1 R278.1 R279.1 R281.1 U30.S
GND: C145.2 C148.2 C151.2 C152.2 C153.2 C155.2 C157.2 C159.1 C161.1 C163.1 C164.1 C165.2 C166.2 C167.2 C168.1 C169.1 C170.1 C171.1 C172.2 C173.2 J37.1 J38.1 Q7.S Q8.S Q9.S Q10.S U29.3(DGND) U29.16(SPKRGND) U29.21(SPKLGND) U29.30(HPGND) U29.34(HPSNS) U29.47(AGND) U29.57(EP)
AUD_I2C_SCL: U29.51(SCL) ; port AUD_I2C_SCL
AUD_I2C_SDA: U29.52(SDA) ; port AUD_I2C_SDA
AUD_INT#: R268.2 U29.56(IRQ#) ; port AUD_INT#
AUD_PWR_EN: Q7.G Q9.G R281.2 R285.2 ; port AUD_PWR_EN
LINE1_IN_L: L35.1 ; port LINE1_IN_L
LINE1_IN_R: L34.1 ; port LINE1_IN_R
LINE2_IN_L: L37.1 ; port LINE2_IN_L
LINE2_IN_R: L36.1 ; port LINE2_IN_R
LINE_OUT_L: U29.24(RECP/LOUTL/RXINP) ; port LINE_OUT_L
LINE_OUT_R: U29.23(RECN/LOUTR/RXINN) ; port LINE_OUT_R
MIC_BIAS: C146.2 L32.2 R273.1 U29.45(JACKSNS)
MIC_N: L33.1 R275.1
MIC_P: L32.1 R274.1
PCM_CLK: R269.1 ; port PCM_CLK
PCM_IN: R272.1 ; port PCM_IN
PCM_OUT: R271.1 ; port PCM_OUT
PCM_SYNC: R270.1 ; port PCM_SYNC
RXD_MAX98089: U29.7(SDOUTS1) ; port RXD_MAX98089
SAI2_MCLK: U29.5(MCLK) ; port SAI2_MCLK
SPKL_N: U29.22(SPKLN) ; port SPKL_N
SPKL_P: U29.20(SPKLP) ; port SPKL_P
SPKR_N: U29.15(SPKRN) ; port SPKR_N
SPKR_P: U29.17(SPKRP) ; port SPKR_P
TXC_MAX98089: U29.8(BCLKS1) ; port TXC_MAX98089
TXD_MAX98089: U29.9(SDINS1) ; port TXD_MAX98089
TXFS_MAX98089: U29.10(LRCLKS1) ; port TXFS_MAX98089
NetC145_1: C145.1 R273.2 U29.44(MICBIAS)
NetC146_1: C146.1 U29.42(MIC2P)
NetC147_1: C147.1 U29.43(MIC2N)
NetC147_2: C147.2 L33.2
NetC148_1: C148.1 C149.1 U29.39(INA1/EXTMICP)
NetC149_2: C149.2 L34.2
NetC150_1: C150.1 C152.1 U29.38(INA2/EXTMICN)
NetC150_2: C150.2 L35.2
NetC151_1: C151.1 R276.1 U29.35(HPR)
NetC153_1: C153.1 C154.1 U29.37(INB1)
NetC154_2: C154.2 L36.2
NetC155_1: C155.1 R277.1 U29.33(HPL)
NetC156_1: C156.1 C157.1 U29.36(INB2)
NetC156_2: C156.2 L37.2
NetC158_1: C158.1 Q7.D Q8.G R279.2 U30.G
NetC160_1: C160.1 U29.27(CIN)
NetC160_2: C160.2 U29.26(C1P)
NetC162_1: C162.1 Q9.D Q10.G R283.2 U16.G
NetC163_2: C163.2 U29.32(HPVDD)
NetC168_2: C168.2 U29.31(HPVSS)
NetC169_2: C169.2 U29.48(REF)
NetC170_2: C170.2 U29.49(REG)
NetJ37_2: J37.2 R275.2
NetJ37_3: J37.3 R274.2
NetJ38_2: J38.2 R277.2
NetJ38_3: J38.3 R276.2
NetQ8_D: Q8.D R280.2
NetQ10_D: Q10.D R284.2
NetR269_2: R269.2 U29.2(BCLKS2)
NetR270_2: R270.2 U29.4(LRCLKS2)
NetR271_2: R271.2 U29.54(SDINS2)
NetR272_2: R272.2 U29.1(SDOUTS2)

Not connected (* = marked no-connect by the designer): U29 11(NC)* 12(NC)* 13(NC)* 14(NC)* 28(NC)* 29(NC)* 40(MIC1P/DIGMICDATA)* 41(MIC1N/DIGMICCLK)* 46(NC)*

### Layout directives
differential pair: MIC_N, MIC_P, SPKL_N, SPKL_P, SPKR_N, SPKR_P

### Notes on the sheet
- AUDIO

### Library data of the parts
C145-C147 C149 C150 C154 C156 = 1000073: CAP CER 1UF 6.3V 20% X5R 0402; Part_Type: Capacitor; Manufacturer: Murata; Manufacturer_Part_Number: GRM155R60J105ME19D; Digi_PN: 14050543; Component_Life_Cycle_State: Proven; Area: 0.95; Project: Adjustable Foundation
C148 C151-C153 C155 C157 = 1001541: CAP CER 10PF 50V 5% NP0 0402; Part_Type: Capacitor; Manufacturer: Murata; Manufacturer_Part_Number: GRM1555C1H100JA01D; Note: 14050750 = Digi No. for GE WDNU; Digi_PN: 14050362; Component_Life_Cycle_State: Reviewed; Area: 0,95; Project: KITT v0.4; Tolerance: 5; Temp_Coef: C0G, NP0
C158 C162 = 1002727: as C87 on sheet 13 - MIPI to HDMI bridge
C159 C161 = 1000006: CAP 100nF 16V 10% X7R 0402; Part_Type: Capacitor; Manufacturer: Murata; Manufacturer_Part_Number: GRM155R71C104KA88D; Digi_PN: 14050552; Component_Life_Cycle_State: CAD Reviewed; Area: 0.95; Project: KITT; Tolerance: 10
C160 C163 C165-C168 C170 C172 C173 = 1001167: as C109 on sheet 14 - MIPI to LVDS bridge
C164 C171 = 1001168: as C82 on sheet 13 - MIPI to HDMI bridge
C169 = 1001303: CAP CER 2.2UF 16V 10% X5R 0603; Part_Type: Capacitor; Manufacturer: TDK Corporation; Manufacturer_Part_Number: C1608X5R1C225K080AB; Digi_PN: 14050730; Component_Life_Cycle_State: Reviewed; Area: 2,27; Project: Pinnacle
J37 J38 = 1002596: CONN JACK STEREO 3.5MM R/A; Part_Type: Connector; Manufacturer: CUI Inc.; Digi_PN: 18000594; Component_Life_Cycle_State: Reviewed; Area: 163.02; Project: CCWMX6_SBC board
L32-L37 = 1002041: FERRITE BEAD 1.8 KOHM 0402 1LN; Manufacturer: Murata; Manufacturer_Part_Number: BLM15HD182SN1D; Digi_PN: 21000461; Component_Life_Cycle_State: Reviewed; Area: 2.2; Project: iMX6UL+PMIC
Q7 = 1000715: as Q4 on sheet 15 - USB HUB
Q8-Q10 = 1000306: as Q5 on sheet 15 - USB HUB
R268 R279 R283 = 1000537: as R225 on sheet 13 - MIPI to HDMI bridge
R269-R272 R274-R277 = 1000076: as R328 on sheet 13 - MIPI to HDMI bridge
R273 = 1001156: RES 2.20K OHM 1/16W 1% 0402 SMD; Part_Type: Resistor; Manufacturer: Yageo; Manufacturer_Part_Number: RC0402FR-072K2L; Note: 13051099 = Digi No. for GE WDNU; Digi_PN: 13050699; Component_Life_Cycle_State: Reviewed; Area: 0,95; Project: CCWMX6_SBC board
R278 R282 = 1000208: as R257 on sheet 15 - USB HUB
R280 R284 = 1001158: as R259 on sheet 15 - USB HUB
R281 R285 = 1000480: as R260 on sheet 15 - USB HUB
U16 U30 = 1001163: as U26 on sheet 15 - USB HUB
U29 = 1002001: IC CODEC AUDIO FLEXSOUND 56TQFN; Manufacturer: Maxim; Manufacturer_Part_Number: MAX98089ETN+T; Component_Life_Cycle_State: Reviewed; Area: 49; Project: iMX6UL+PMIC; Digi_PN: 16052036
